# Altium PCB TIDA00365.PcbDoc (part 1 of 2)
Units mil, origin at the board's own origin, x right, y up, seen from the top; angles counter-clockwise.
Board outline 2520 x 2690 mil, 4 copper layers (Top Layer, Mid Layer, GND Layer, Bottom Layer), stack 69.2 mil thick; 171 components, 86 nets, 427 pads, 370 vias.
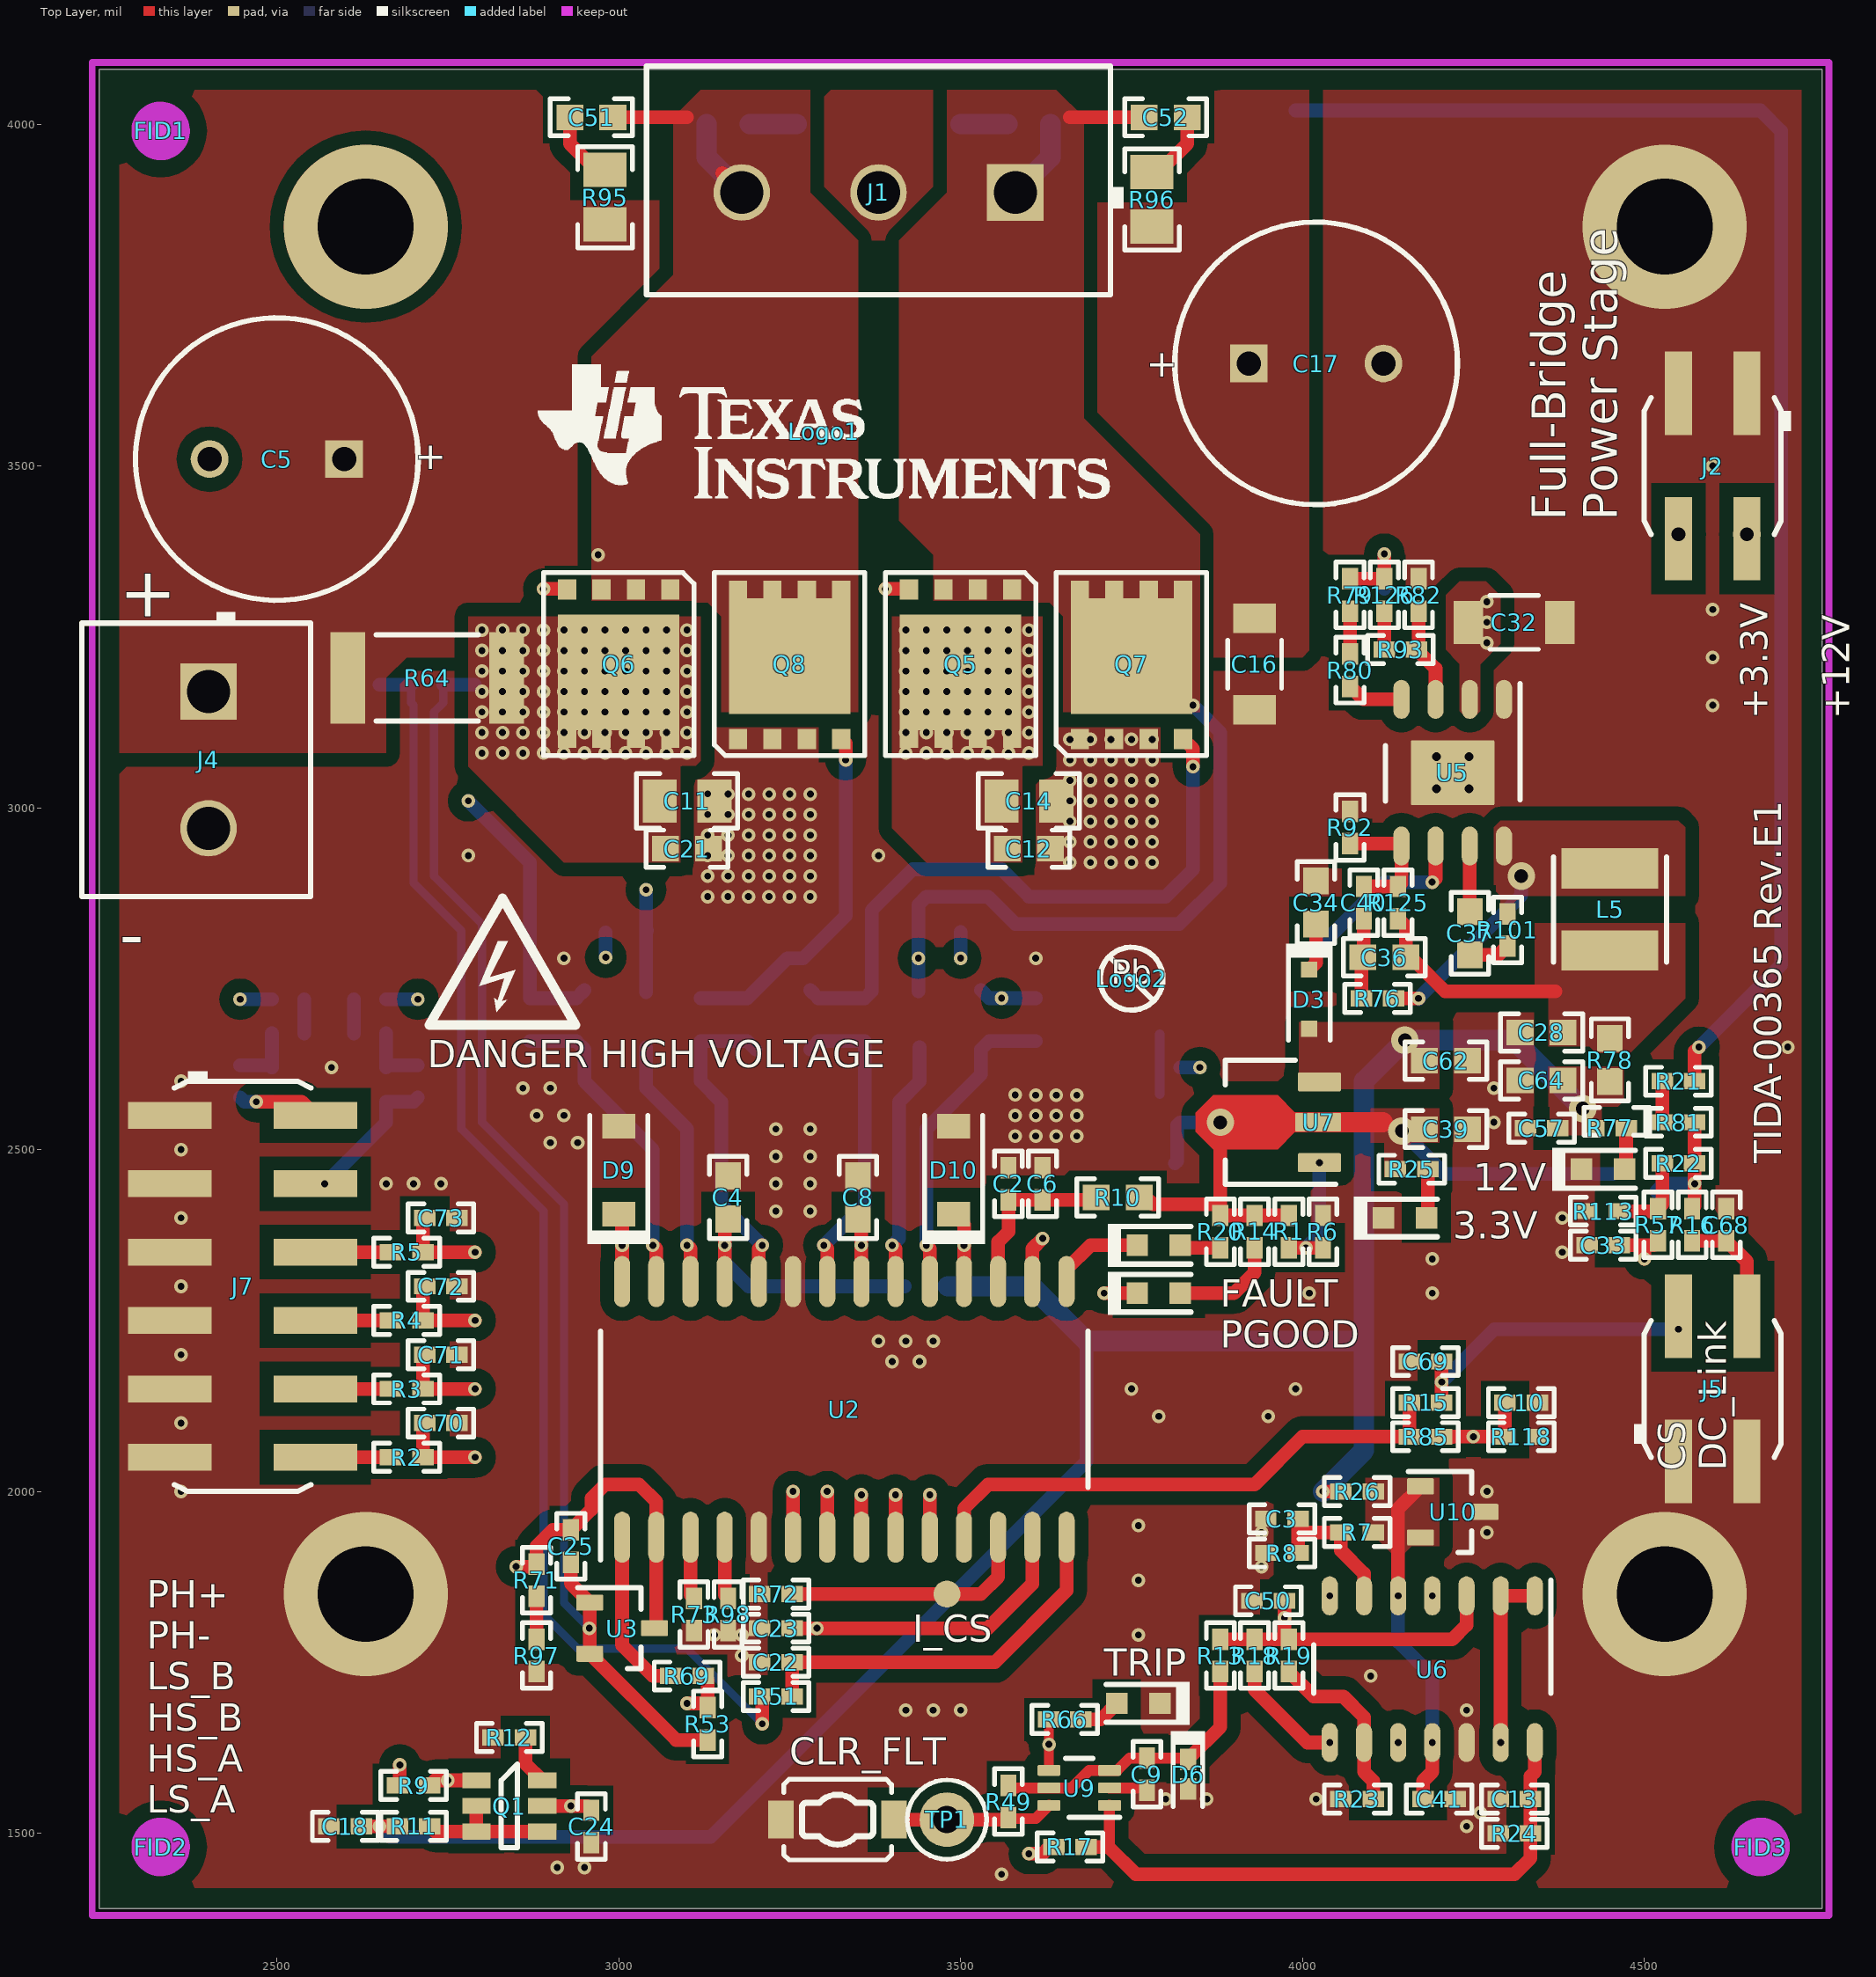
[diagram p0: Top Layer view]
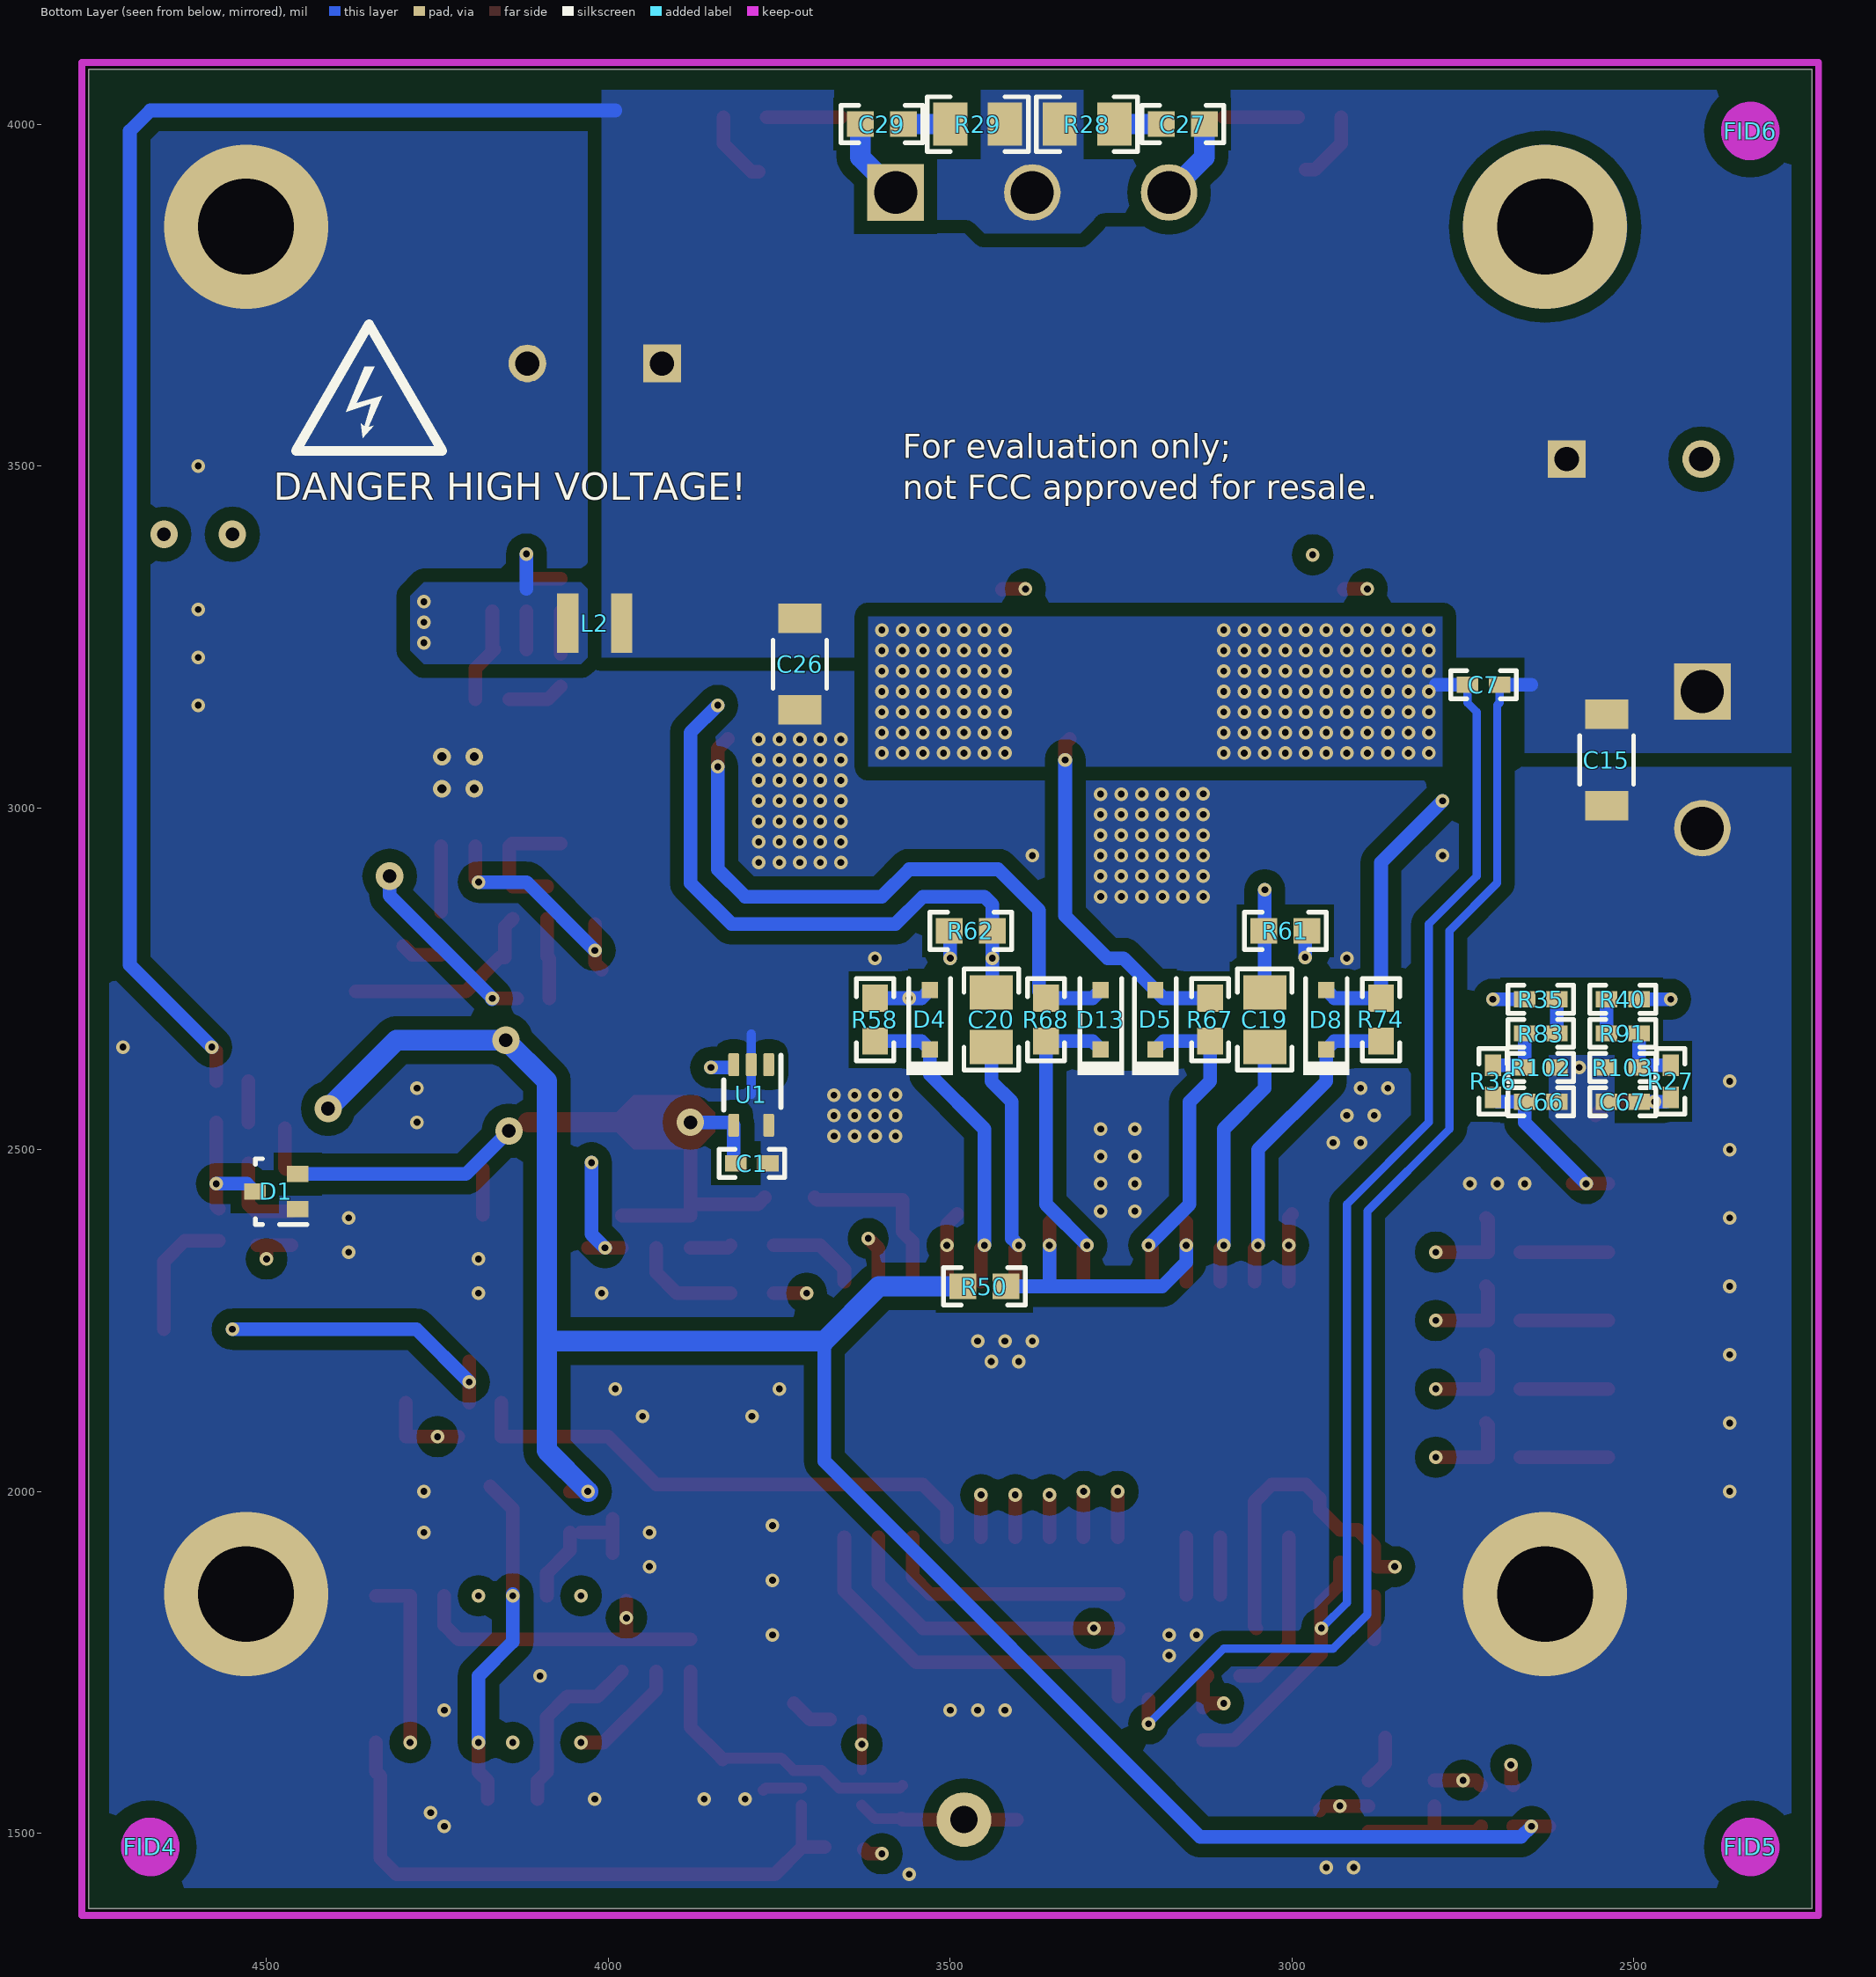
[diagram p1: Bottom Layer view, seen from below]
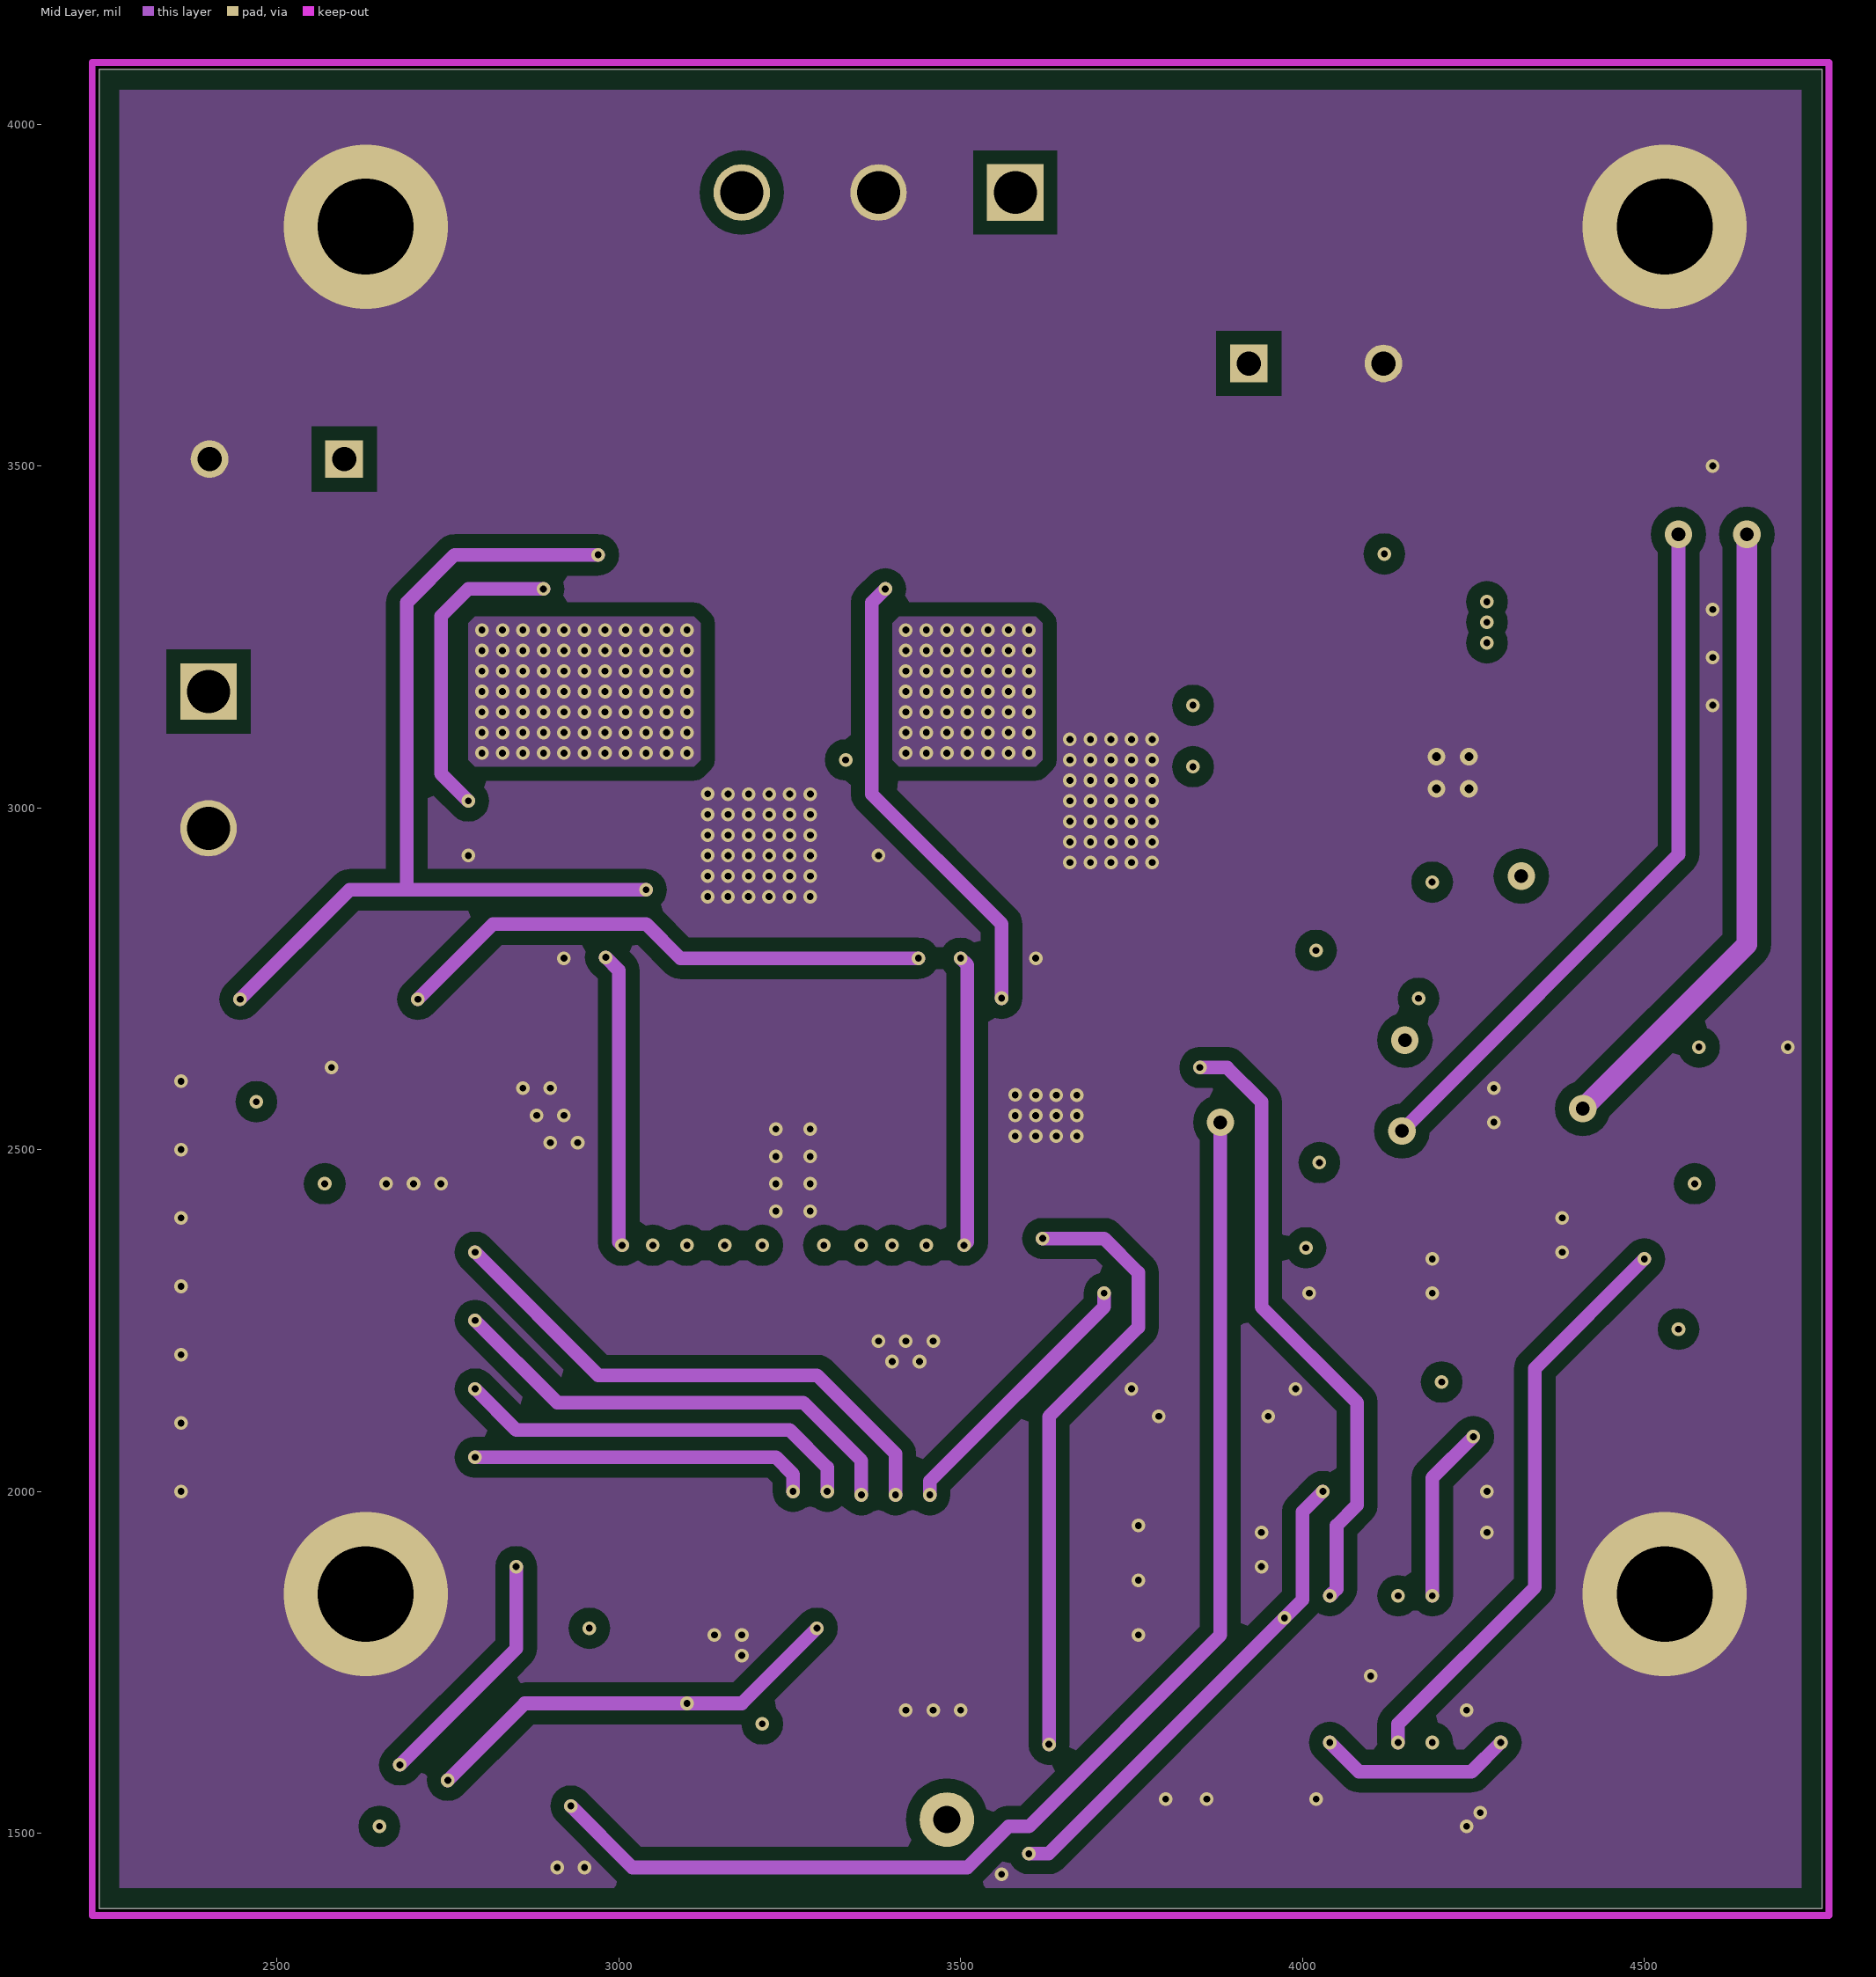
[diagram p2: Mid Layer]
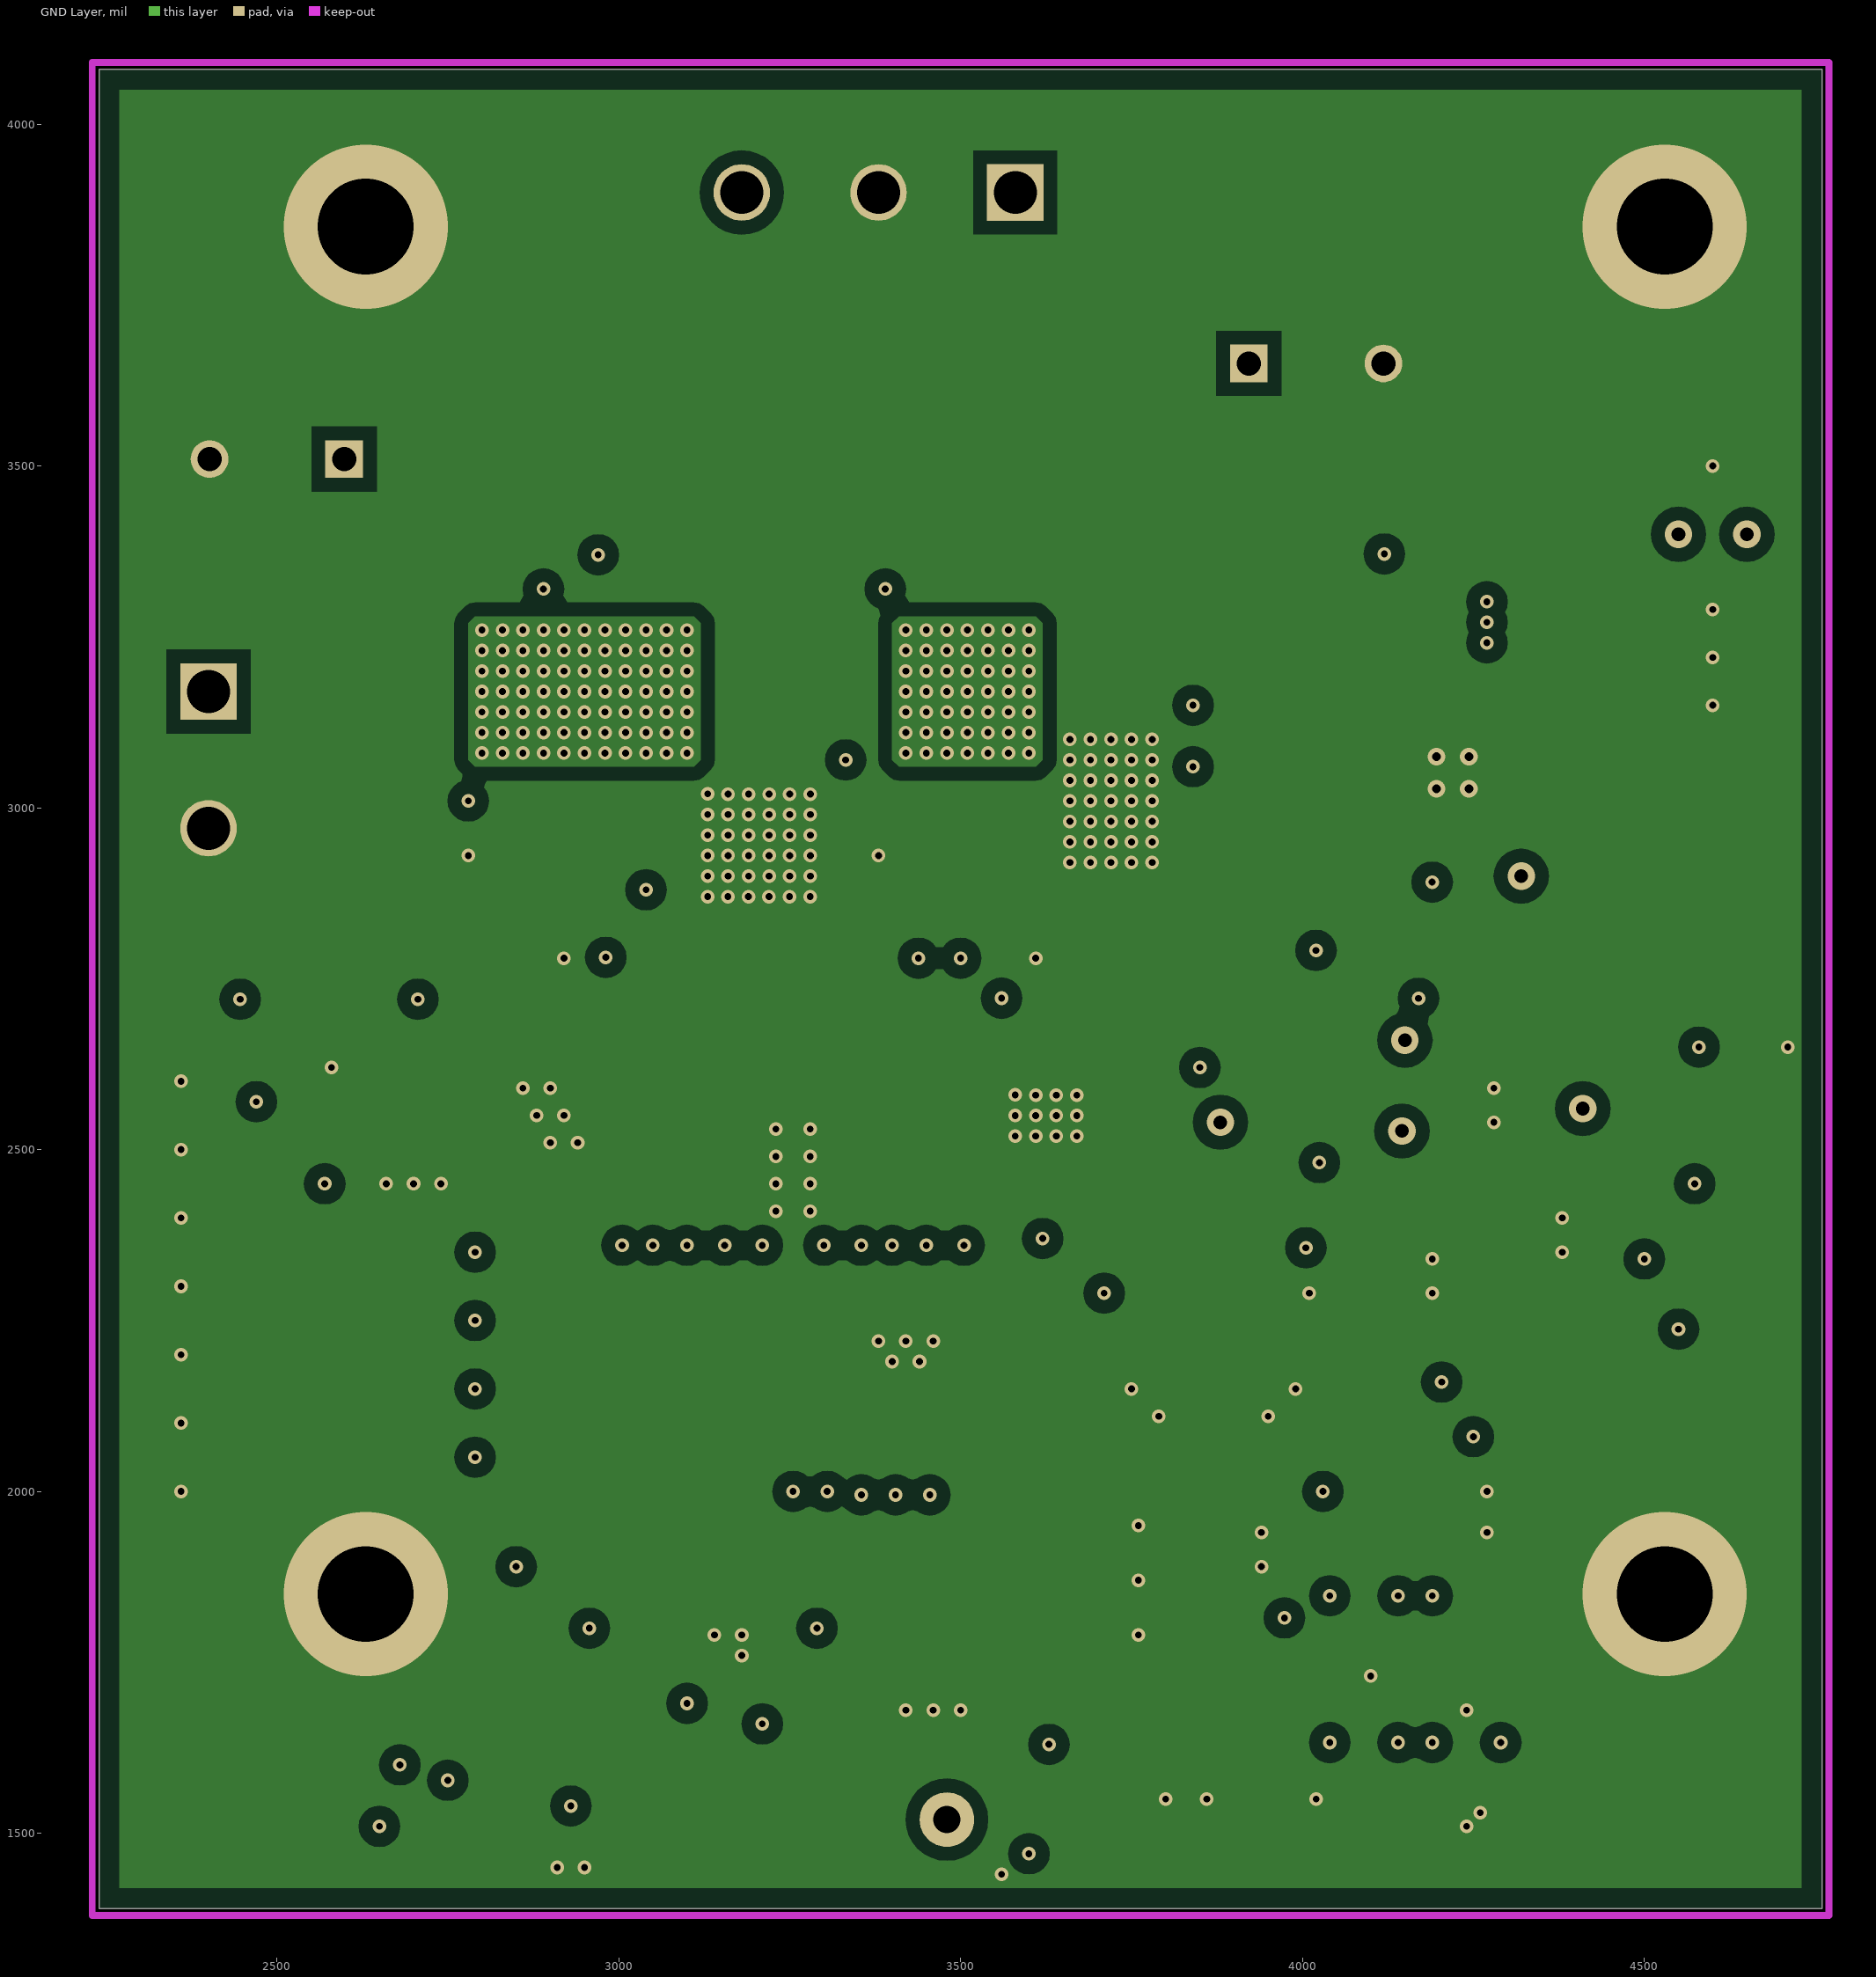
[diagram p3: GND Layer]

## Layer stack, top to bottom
Top Solder: solder mask 0.4, Solder Resist, Dk 3.5
Top Layer: signal copper 2.8
Dielectric: prepreg 12, FR-4, Dk 4.2
Mid Layer: signal copper 2.8
Dielectric: core 34, FR-4, Dk 4.2
GND Layer: signal copper 2.8
Dielectric: prepreg 12, FR-4, Dk 4.2
Bottom Layer: signal copper 2.8
Solder Side: solder mask 0.4, Solder Resist, Dk 3.5

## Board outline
2240,1390 2240,4080 4760,4080 4760,1390

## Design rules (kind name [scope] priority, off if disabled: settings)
AcuteAngle [All] p1: minimum=4.50000000000000E+0001 checktracksonly=FALSE
AssemblyTestPointUsage [All] p1: valid=2
Clearance Clearance_Keepouts [((IsTrack Or IsArc) And Not InPoly) And IsFree and IsKeepOut vs ((IsTrack Or IsArc) And Not InPoly) And IsFree and IsKeepOut] p1: gap=10
Clearance Clearance_BoardEdge_MountingHoles [OnCopper and InComponentClass('Mounting Holes') vs IsKeepOut] p2: gap=10
Clearance Clearance_BoardEdge_Poly [OnCopper and InPoly vs IsKeepOut] p3: gap=25
Clearance Clearance_BoardEdge [OnCopper and Not InComponentClass('Logo') and not InComponentClass('FiducialMark') and not InRegion(1000,500,4000,800) and Not IsKeepout vs IsKeepOut] p4: gap=25
Clearance Clearance_Poly [InPolygon] p5: gap=20
Clearance [All] p6: gap=8
ComponentClearance ComponentClearance_MountingHoles_FiducialMarks [InComponentClass('Mounting Holes') vs InComponentClass('FiducialMark')] p1: gap=20 collisioncheckmode=3 verticalgap=10 showdistances=FALSE
ComponentClearance ComponentClearance_Shunt [InComponentClass('Header') vs InComponentClass('Shunt')] p2: gap=0 collisioncheckmode=3 verticalgap=0 showdistances=FALSE
ComponentClearance ComponentClearance_Logo [InComponentClass('Logo')] p3: gap=10 collisioncheckmode=3 verticalgap=10 showdistances=FALSE
ComponentClearance ComponentClearance_ScrewToNut [(HasFootprint('NY PMS 440 0025 PH')) vs (HasFootprint('Keystone_1902C'))] p4: gap=5 collisioncheckmode=3 verticalgap=10 showdistances=FALSE
ComponentClearance ComponentClearance_MountingHoles [InComponentClass('Mounting Holes')] p5: gap=20 collisioncheckmode=3 verticalgap=100000 showdistances=FALSE
ComponentClearance ComponentClearance_SmallPassives [HasFootprint('0201*') or HasFootprint('0402*') or HasFootprint('0508') or HasFootprint('0603*') or HasFootprint('0612') or HasFootprint('0805*') or HasFootprint('0815*') or HasFootprint('0830*') or HasFootprint('1206*') or HasFootprint('1210*') or HasFootprint('1808*') or HasFootprint('1812*') or HasFootprint('1825*') or HasFootprint('2010*') or HasFootprint('2220*') or HasFootprint('2225*') or HasFootprint('2512*') or HasFootprint('2728*') or HasFootprint('3518*') vs HasFootprint('0201*') or HasFootprint('0402*') or HasFootprint('0508') or HasFootprint('0603*') or HasFootprint('0612') or HasFootprint('0805*') or HasFootprint('0815*') or HasFootprint('0830*') or HasFootprint('1206*') or HasFootprint('1210*') or HasFootprint('1808*') or HasFootprint('1812*') or HasFootprint('1825*') or HasFootprint('2010*') or HasFootprint('2220*') or HasFootprint('2225*') or HasFootprint('2512*') or HasFootprint('2728*') or HasFootprint('3518*')] p6: gap=20 collisioncheckmode=3 verticalgap=10 showdistances=FALSE
ComponentClearance ComponentClearance_THtoSMT [IsThruComponent vs IsSMTComponent] p7: gap=20 collisioncheckmode=3 verticalgap=30 showdistances=FALSE
ComponentClearance ComponentClearance_THtoTH [IsThruComponent vs IsThruComponent] p8: gap=20 collisioncheckmode=3 verticalgap=30 showdistances=FALSE
ComponentClearance [All] p9: gap=25 collisioncheckmode=3 verticalgap=10 showdistances=FALSE
DiffPairsRouting [All] p1: maxlimit=100 minlimit=10 mostfreqgap=10 toplayer_minwidth=15 toplayer_maxwidth=15 toplayer_prefwidth=15 midlayer1_minwidth=15 midlayer1_maxwidth=15 midlayer1_prefwidth=15 midlayer2_minwidth=15 midlayer2_maxwidth=15 midlayer2_prefwidth=15 bottomlayer_minwidth=15 bottomlayer_maxwidth=15 bottomlayer_prefwidth=15 maxuncoupledlength=1000
FabricationTestPointUsage TestPointUsage [All] p1: valid=2 allowmultiple=FALSE
FabricationTestpoint Testpoint [All] p1: side=3 testpointundercomponent=TRUE minsize=40 maxsize=100 preferedsize=60 minholesize=0 maxholesize=40 preferedholesize=32 testpointgrid=1 allowsidetop=TRUE allowsidebottom=TRUE usegrid=TRUE gridtolerance=0.01
FanoutControl Fanout_LCC [IsLCC] p1: bgadir=Out bgaviamode=Centered fanoutstyle=Auto fanoutdirection=Alternating viagrid=1 // Fanout_LCC (Default Rule)
FanoutControl Fanout_BGA [IsBGA] p2: bgadir=Out bgaviamode=Centered fanoutstyle=Auto fanoutdirection=Alternating viagrid=1 // Fanout_BGA (Default Rule)
FanoutControl Fanout_Default [All] p4: bgadir=Out bgaviamode=Centered fanoutstyle=Auto fanoutdirection=Alternating viagrid=1 // Fanout_Default (Default Rule)
FanoutControl Fanout_Small [(CompPinCount < 5)] p5: bgadir=Out bgaviamode=Centered fanoutstyle=Auto fanoutdirection=OutThenIn viagrid=1 // Fanout_Small (Default Rule)
HoleSize [All] p1: absolutevalues=TRUE maxlimit=251 minlimit=8 maxpercent=80.000 minpercent=20.000
MinimumAnnularRing MinimumAnnularRing_ThermalPadVias [IsVia and InAnyComponent] p1: minimumring=6
MinimumAnnularRing [All] p2: minimumring=4
MinimumSolderMaskSliver MinimumSolderMaskSliver_Logo [InComponentClass('Logo') vs InComponentClass('Logo')] p1: minsoldermaskwidth=0.7
MinimumSolderMaskSliver [All] p2: minsoldermaskwidth=0
PlaneConnect [All] p1: planeconnectstyle=Relief reliefexpansion=10 reliefentries=4 reliefconductorwidth=10 reliefairgap=10
PolygonConnect PolygonConnect_59 [All vs IsNamedPolygon('GND_L04_P043')] p1: connectstyle=Direct reliefconductorwidth=10 reliefentries=4 polygonreliefangle="90 Angle" airgapwidth=10
PolygonConnect PolygonConnect_58 [All vs IsNamedPolygon('PROT_VTH_L01_P044')] p2: connectstyle=Direct reliefconductorwidth=10 reliefentries=4 polygonreliefangle="90 Angle" airgapwidth=10
PolygonConnect PolygonConnect_57 [All vs IsNamedPolygon('NONET_L04_P125')] p3: connectstyle=Direct reliefconductorwidth=10 reliefentries=4 polygonreliefangle="90 Angle" airgapwidth=10
PolygonConnect PolygonConnect_56 [All vs IsNamedPolygon('NONET_L04_P127')] p4: connectstyle=Direct reliefconductorwidth=10 reliefentries=4 polygonreliefangle="90 Angle" airgapwidth=10
PolygonConnect PolygonConnect_55 [All vs IsNamedPolygon('HS_CSN_2_L03_P049')] p5: connectstyle=Direct reliefconductorwidth=10 reliefentries=4 polygonreliefangle="90 Angle" airgapwidth=10
PolygonConnect PolygonConnect_54 [All vs IsNamedPolygon('HS_CSN_2_L03_P048')] p6: connectstyle=Direct reliefconductorwidth=10 reliefentries=4 polygonreliefangle="90 Angle" airgapwidth=10
PolygonConnect PolygonConnect_53 [All vs IsNamedPolygon('HS_CSN_2_L02_P050')] p7: connectstyle=Direct reliefconductorwidth=10 reliefentries=4 polygonreliefangle="90 Angle" airgapwidth=10
PolygonConnect PolygonConnect_52 [All vs IsNamedPolygon('HS_CSN_2_L02_P051')] p8: connectstyle=Direct reliefconductorwidth=10 reliefentries=4 polygonreliefangle="90 Angle" airgapwidth=10
PolygonConnect PolygonConnect_51 [All vs IsNamedPolygon('NETC32_1_L01_P052')] p9: connectstyle=Direct reliefconductorwidth=10 reliefentries=4 polygonreliefangle="90 Angle" airgapwidth=10
PolygonConnect PolygonConnect_50 [All vs IsNamedPolygon('HS_CSN_2_L04_P053')] p10: connectstyle=Direct reliefconductorwidth=10 reliefentries=4 polygonreliefangle="90 Angle" airgapwidth=10
PolygonConnect PolygonConnect_49 [All vs IsNamedPolygon('HS_CSN_2_L04_P053')] p11: connectstyle=Direct reliefconductorwidth=10 reliefentries=4 polygonreliefangle="90 Angle" airgapwidth=10
PolygonConnect PolygonConnect_48 [All vs IsNamedPolygon('HS_CSN_2_L01_P054')] p12: connectstyle=Direct reliefconductorwidth=10 reliefentries=4 polygonreliefangle="90 Angle" airgapwidth=10
PolygonConnect PolygonConnect_47 [All vs IsNamedPolygon('PHASEB+_L01_P056')] p13: connectstyle=Direct reliefconductorwidth=10 reliefentries=4 polygonreliefangle="90 Angle" airgapwidth=10
PolygonConnect PolygonConnect_46 [All vs IsNamedPolygon('HS_CSN_2_L01_P057')] p14: connectstyle=Direct reliefconductorwidth=10 reliefentries=4 polygonreliefangle="90 Angle" airgapwidth=10
PolygonConnect PolygonConnect_45 [All vs IsNamedPolygon('HS_CSP_2_L01_P058')] p15: connectstyle=Direct reliefconductorwidth=10 reliefentries=4 polygonreliefangle="90 Angle" airgapwidth=10
PolygonConnect PolygonConnect_44 [All vs IsNamedPolygon('PHASEB+_L01_P056')] p16: connectstyle=Direct reliefconductorwidth=10 reliefentries=4 polygonreliefangle="90 Angle" airgapwidth=10
PolygonConnect PolygonConnect_43 [All vs IsNamedPolygon('PHASEB-_L01_P055')] p17: connectstyle=Direct reliefconductorwidth=10 reliefentries=4 polygonreliefangle="90 Angle" airgapwidth=10
PolygonConnect PolygonConnect_42 [All vs IsNamedPolygon('GND_L02_P079')] p18: connectstyle=Direct reliefconductorwidth=10 reliefentries=4 polygonreliefangle="90 Angle" airgapwidth=10
PolygonConnect PolygonConnect_41 [All vs IsNamedPolygon('GND_L04_P077')] p19: connectstyle=Direct reliefconductorwidth=10 reliefentries=4 polygonreliefangle="90 Angle" airgapwidth=10
PolygonConnect PolygonConnect_40 [All vs IsNamedPolygon('GND_L01_P115')] p20: connectstyle=Direct reliefconductorwidth=10 reliefentries=4 polygonreliefangle="90 Angle" airgapwidth=10
PolygonConnect PolygonConnect_39 [All vs IsNamedPolygon('HS_CSP_2_L04_P063')] p21: connectstyle=Direct reliefconductorwidth=10 reliefentries=4 polygonreliefangle="90 Angle" airgapwidth=10
PolygonConnect PolygonConnect_38 [All vs IsNamedPolygon('HS_CSP_2_L04_P063')] p22: connectstyle=Direct reliefconductorwidth=10 reliefentries=4 polygonreliefangle="90 Angle" airgapwidth=10
PolygonConnect PolygonConnect_37 [All vs IsNamedPolygon('HS_CSP_2_L04_P063')] p23: connectstyle=Direct reliefconductorwidth=10 reliefentries=4 polygonreliefangle="90 Angle" airgapwidth=10
PolygonConnect PolygonConnect_36 [All vs IsNamedPolygon('HS_CSN_2_L04_P072')] p24: connectstyle=Direct reliefconductorwidth=10 reliefentries=4 polygonreliefangle="90 Angle" airgapwidth=10
PolygonConnect PolygonConnect_35 [All vs IsNamedPolygon('HS_CSP_2_L01_P061')] p25: connectstyle=Direct reliefconductorwidth=10 reliefentries=4 polygonreliefangle="90 Angle" airgapwidth=10
PolygonConnect PolygonConnect_34 [All vs IsNamedPolygon('Mid Layer-No Net')] p26: connectstyle=Direct reliefconductorwidth=10 reliefentries=4 polygonreliefangle="90 Angle" airgapwidth=10
PolygonConnect PolygonConnect_33 [All vs IsNamedPolygon('NETC28_1_L01_P073')] p27: connectstyle=Direct reliefconductorwidth=10 reliefentries=4 polygonreliefangle="90 Angle" airgapwidth=10
PolygonConnect PolygonConnect_32 [All vs IsNamedPolygon('Bottom Layer-No Net 4')] p28: connectstyle=Direct reliefconductorwidth=10 reliefentries=4 polygonreliefangle="90 Angle" airgapwidth=10
PolygonConnect PolygonConnect_31 [All vs IsNamedPolygon('GND Layer-No Net')] p29: connectstyle=Direct reliefconductorwidth=10 reliefentries=4 polygonreliefangle="90 Angle" airgapwidth=10
PolygonConnect PolygonConnect_30 [All vs IsNamedPolygon('Top Layer-No Net 16')] p30: connectstyle=Direct reliefconductorwidth=10 reliefentries=4 polygonreliefangle="90 Angle" airgapwidth=10
PolygonConnect PolygonConnect_29 [All vs IsNamedPolygon('Top Layer-No Net 15')] p31: connectstyle=Direct reliefconductorwidth=10 reliefentries=4 polygonreliefangle="90 Angle" airgapwidth=10
PolygonConnect PolygonConnect_28 [All vs IsNamedPolygon('Top Layer-No Net 14')] p32: connectstyle=Direct reliefconductorwidth=10 reliefentries=4 polygonreliefangle="90 Angle" airgapwidth=10
PolygonConnect PolygonConnect_27 [All vs IsNamedPolygon('Top Layer-No Net 13')] p33: connectstyle=Direct reliefconductorwidth=10 reliefentries=4 polygonreliefangle="90 Angle" airgapwidth=10
PolygonConnect PolygonConnect_26 [All vs IsNamedPolygon('NETL5_1_L01_P067')] p34: connectstyle=Direct reliefconductorwidth=10 reliefentries=4 polygonreliefangle="90 Angle" airgapwidth=10
PolygonConnect PolygonConnect_25 [All vs IsNamedPolygon('+12V_L01_P064')] p35: connectstyle=Direct reliefconductorwidth=10 reliefentries=4 polygonreliefangle="90 Angle" airgapwidth=10
PolygonConnect PolygonConnect_24 [All vs IsNamedPolygon('+12V_L01_P074')] p36: connectstyle=Direct reliefconductorwidth=10 reliefentries=4 polygonreliefangle="90 Angle" airgapwidth=10
PolygonConnect PolygonConnect_23 [All vs IsNamedPolygon('Bottom Layer-No Net 3')] p37: connectstyle=Direct reliefconductorwidth=10 reliefentries=4 polygonreliefangle="90 Angle" airgapwidth=10
PolygonConnect PolygonConnect_22 [All vs IsNamedPolygon('Bottom Layer-No Net 2')] p38: connectstyle=Direct reliefconductorwidth=10 reliefentries=4 polygonreliefangle="90 Angle" airgapwidth=10
PolygonConnect PolygonConnect_21 [All vs IsNamedPolygon('Bottom Layer-No Net 1')] p39: connectstyle=Direct reliefconductorwidth=10 reliefentries=4 polygonreliefangle="90 Angle" airgapwidth=10
PolygonConnect PolygonConnect_20 [All vs IsNamedPolygon('Bottom Layer-No Net')] p40: connectstyle=Direct reliefconductorwidth=10 reliefentries=4 polygonreliefangle="90 Angle" airgapwidth=10
PolygonConnect PolygonConnect_19 [All vs IsNamedPolygon('Bottom Layer-No Net 1')] p41: connectstyle=Direct reliefconductorwidth=10 reliefentries=4 polygonreliefangle="90 Angle" airgapwidth=10
PolygonConnect PolygonConnect_18 [All vs IsNamedPolygon('GND_L03_P078')] p42: connectstyle=Direct reliefconductorwidth=10 reliefentries=4 polygonreliefangle="90 Angle" airgapwidth=10
PolygonConnect PolygonConnect_17 [All vs IsNamedPolygon('GND_L03_P078')] p43: connectstyle=Direct reliefconductorwidth=10 reliefentries=4 polygonreliefangle="90 Angle" airgapwidth=10
PolygonConnect PolygonConnect_16 [All vs IsNamedPolygon('GND_L03_P078')] p44: connectstyle=Direct reliefconductorwidth=10 reliefentries=4 polygonreliefangle="90 Angle" airgapwidth=10
PolygonConnect PolygonConnect_15 [All vs IsNamedPolygon('GND_L03_P078')] p45: connectstyle=Direct reliefconductorwidth=10 reliefentries=4 polygonreliefangle="90 Angle" airgapwidth=10
PolygonConnect PolygonConnect_14 [All vs IsNamedPolygon('GND_L03_P078')] p46: connectstyle=Direct reliefconductorwidth=10 reliefentries=4 polygonreliefangle="90 Angle" airgapwidth=10
PolygonConnect PolygonConnect_13 [All vs IsNamedPolygon('NETC32_1_L04_P065')] p47: connectstyle=Direct reliefconductorwidth=10 reliefentries=4 polygonreliefangle="90 Angle" airgapwidth=10
PolygonConnect PolygonConnect_12 [All vs IsNamedPolygon('NETL5_1_L01_P067')] p48: connectstyle=Direct reliefconductorwidth=10 reliefentries=4 polygonreliefangle="90 Angle" airgapwidth=10
PolygonConnect PolygonConnect_11 [All vs IsNamedPolygon('+3V3_L01_P045')] p49: connectstyle=Direct reliefconductorwidth=10 reliefentries=4 polygonreliefangle="90 Angle" airgapwidth=10
PolygonConnect PolygonConnect_10 [All vs IsNamedPolygon('+3V3_L01_P045')] p50: connectstyle=Direct reliefconductorwidth=10 reliefentries=4 polygonreliefangle="90 Angle" airgapwidth=10
PolygonConnect PolygonConnect_9 [All vs IsNamedPolygon('NETC32_1_L04_P065')] p51: connectstyle=Direct reliefconductorwidth=10 reliefentries=4 polygonreliefangle="90 Angle" airgapwidth=10
PolygonConnect PolygonConnect_8 [All vs IsNamedPolygon('NETL5_1_L01_P067')] p52: connectstyle=Direct reliefconductorwidth=10 reliefentries=4 polygonreliefangle="90 Angle" airgapwidth=10
PolygonConnect PolygonConnect_7 [All vs IsNamedPolygon('NETC28_1_L01_P073')] p53: connectstyle=Direct reliefconductorwidth=10 reliefentries=4 polygonreliefangle="90 Angle" airgapwidth=10
PolygonConnect PolygonConnect_6 [All vs IsNamedPolygon('+3V3_L01_P045')] p54: connectstyle=Direct reliefconductorwidth=10 reliefentries=4 polygonreliefangle="90 Angle" airgapwidth=10
PolygonConnect PolygonConnect_5 [All vs IsNamedPolygon('+3V3_L01_P045')] p55: connectstyle=Direct reliefconductorwidth=10 reliefentries=4 polygonreliefangle="90 Angle" airgapwidth=10
PolygonConnect PolygonConnect_4 [All vs IsNamedPolygon('Top Layer-No Net 3')] p56: connectstyle=Direct reliefconductorwidth=10 reliefentries=4 polygonreliefangle="90 Angle" airgapwidth=10
PolygonConnect PolygonConnect_3 [All vs IsNamedPolygon('Top Layer-No Net 1')] p57: connectstyle=Direct reliefconductorwidth=10 reliefentries=4 polygonreliefangle="90 Angle" airgapwidth=10
PolygonConnect PolygonConnect_2 [All vs IsNamedPolygon('+12V_L01_P064')] p58: connectstyle=Direct reliefconductorwidth=10 reliefentries=4 polygonreliefangle="90 Angle" airgapwidth=10
PolygonConnect PolygonConnect_1 [All vs IsNamedPolygon('GND_L03_P078')] p59: connectstyle=Direct reliefconductorwidth=10 reliefentries=4 polygonreliefangle="90 Angle" airgapwidth=10
PolygonConnect [All] p60: connectstyle=Direct reliefconductorwidth=10 reliefentries=4 polygonreliefangle="90 Angle" airgapwidth=10
RoutingVias ThermalPadVias [IsVia and InAnyComponent] p1: holewidth=10 width=20 viastyle="Through Hole" minholewidth=5 minwidth=15 maxholewidth=25 maxwidth=45
RoutingVias [All] p2: holewidth=10 width=20 viastyle="Through Hole" minholewidth=5 minwidth=10 maxholewidth=200 maxwidth=300
SilkToBoardRegionClearance [Not ((IsComment or IsDesignator) And (Hide <> 'False')) and not InRegion(1000,500,4000,800)] p1:
SilkToSilkClearance SilkToSilkClearance_Pb-FreeLogo [(HasFootprint('Pb-Free_Overlay_Medium') OR HasFootprint('Pb-Free_Overlay_Small')) vs (HasFootprint('Pb-Free_Overlay_Medium') OR HasFootprint('Pb-Free_Overlay_Small'))] p1: silktosilkclearance=0
SilkToSilkClearance [All] p2: silktosilkclearance=0
SilkToSolderMaskClearance SilkToComonentPadClearance [IsPad and InAnycomponent] p1: minsilkscreentomaskgap=0 clearancetoexposedcopper=TRUE
SilkToSolderMaskClearance "Silk to Solder Mask Opening" [All] p2: minsilkscreentomaskgap=0 clearancetoexposedcopper=FALSE
SolderMaskExpansion [All] p1: expansion=1.97
Width [All] p1: maxlimit=200 minlimit=5 preferedwidth=20 checkconnectedcopper=TRUE
15 further rules are at their usual default settings.

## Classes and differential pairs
component class Logo: Logo1
component class TIDA00365_Screws: "DANGER HIGH VOLTAGE" "DANGER HIGH VOLTAGE1" "DANGER HIGH VOLTAGE!" FID1 FID2 FID3 FID4 FID5 FID6 Logo1 Logo2 Logo3
component class Header: J2 J5 J7
component class Protections: C1 C3 C9 C10 C13 C33 C41 C50 CLR_FLT D1 D6 R7 R8 R13 R17 R18 R19 R21 R22 R23 R24 R26 R49 R57 R66 R81 R85 R113 R118 R? TP1 TRIP U1 U6 U9 U10
component class "Full Bridge": C2 C4 C6 C7 C8 C11 C12 C14 C18 C19 C20 C21 C22 C23 C24 C25 C27 C29 C51 C52 D4 D5 D8 D9 D10 D13 FAULT I_CS PGOOD Q1 Q5 Q6 Q7 Q8 R9 R10 R11 R12 R14 R20 R28 R29 R50 R51 R53 R58 R61 R62 R64 R67 R68 R69 R71 R72 R73 R74 R95 R96 R97 R98 U2 U3
component class "Power Supply": 3.3V 4V 12V C5 C15 C16 C17 C26 C28 C32 C34 C36 C37 C39 C40 C57 C62 C64 D3 J2 J4 L2 L5 R1 R6 R25 R76 R77 R78 R79 R80 R82 R92 R93 R101 R125 R126 U5 U7
component class Interfaces: C66 C67 C68 C69 C70 C71 C72 C73 J1 J5 J7 R2 R3 R4 R5 R15 R16 R27 R35 R36 R40 R83 R91 R102 R103
component class FiducialMark: FID1 FID2 FID3 FID4 FID5 FID6

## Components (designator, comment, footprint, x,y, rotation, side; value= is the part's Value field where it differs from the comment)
3.3V "150060GS75000" WL-SMCW_GREEN 4150,2400 r0 top
12V "150060GS75000" WL-SMCW_GREEN 4439.8,2471.3 r0 top
C1 "C1005X7R1E104M050BB" 0402#1 3790,2480 r180 bottom
C2 "885012205031" 0402#1 3570,2450 r90 top
C3 "885012105016" 0402#1 3970,1960 r180 top
C4 "885012106017" 0603 3160,2430 r270 top
C5 "860040875005" WCAP-ATUL_1000x2500 2500,3510 r180 top
C6 "C1005X7R1E104M050BB" 0402#1 3620,2450 r90 top
C7 "GRM155R72A472KA01D" 0402#1 2720,3180 r0 bottom
C8 "885012106017" 0603 3350,2430 r270 top
C9 "885012205031" 0402#1 3772.65,1586.38 r270 top
C10 "CC0402KRX7R9BB101" 0402#1 4320,2130 r0 top
C11 "C2012X7S2A105K125AB" 0805_HV 3100,3010 r0 top
C12 "06031C103KAT2A" 0603 3600,2940 r0 top
C13 "CC0402KRX7R9BB101" 0402#1 4310,1550 r180 top
C14 "C2012X7S2A105K125AB" 0805_HV 3600,3010 r0 top
C15 "C3216X7S2A335M160AB" 1206_190 2540,3070 r270 bottom
C16 "C3216X7S2A335M160AB" 1206_190 3930,3210 r270 top
C17 "860040875005" WCAP-ATUL_1000x2500 4020,3650 r0 top
C18 "885012205031" 0402#1 2600,1510 r180 top
C19 "C2012X7R2A104K125AA" 0805_HV 3040,2690 r90 bottom
C20 "C2012X7R2A104K125AA" 0805_HV 3440,2690 r90 bottom
C21 "06031C103KAT2A" 0603 3100,2940 r0 top
C22 "885012205055" 0402#1 3230,1750 r0 top
C23 "885012205055" 0402#1 3230,1800 r180 top
C24 "885012205031" 0402#1 2960,1510 r270 top
C25 "885012205055" 0402#1 2930,1920 r90 top
C26 "C3216X7S2A335M160AB" 1206_190 3720,3210 r270 bottom
C27 "06031C222JAT2A" 0603 3160,4000 r180 bottom
C28 "GRM188R61E475KE11D" 0603 4349.8,2671.3 r180 top
C29 "06031C222JAT2A" 0603 3600,4000 r0 bottom
C32 "C3216X7S2A335M160AB" 1206_190 4309.8,3271.3 r0 top
C33 "CC0402KRX7R9BB101" 0402#1 4440,2360 r180 top
C34 "C1608X5R1C105K" 0603 4019.8,2861.3 r90 top
C36 "GRM188R72A332KA01D" 0603 4119.8,2781.3 r180 top
C37 "GRM188R72A104KA35D" 0603 4244.8,2816.3 r270 top
C39 "C1608X5R1C105K" 0603 4210,2530 r0 top
C40 "C1005X7R1E104M050BB" 0402#1 4089.8,2861.3 r90 top
C41 "885012205044" 0402#1 4200,1550 r0 top
C50 "C1005X7R1E104M050BB" 0402#1 3950,1840 r180 top
C51 "06031C222JAT2A" 0603 2960,4010 r0 top
C52 "06031C222JAT2A" 0603 3800,4010 r180 top
C57 "C1005X7R1E104M050BB" 0402#1 4349.8,2531.3 r180 top
C62 "C1608X5R1C105K" 0603 4210,2630 r0 top
C64 "GRM188R61E475KE11D" 0603 4349.8,2601.3 r180 top
C66 "CC0402KRX7R9BB101" 0402#1 2636.38,2570 r0 bottom
C67 "CC0402KRX7R9BB101" 0402#1 2516.38,2570 r180 bottom
C68 "CC0402KRX7R9BB101" 0402#1 4620,2390 r270 top
C69 "CC0402KRX7R9BB101" 0402#1 4180,2190 r0 top
C70 "CC0402KRX7R9BB101" 0402#1 2740,2100 r0 top
C71 "CC0402KRX7R9BB101" 0402#1 2740,2200 r0 top
C72 "CC0402KRX7R9BB101" 0402#1 2740,2300 r0 top
C73 "CC0402KRX7R9BB101" 0402#1 2740,2400 r0 top
CLR_FLT "TL1015AF160QG" SW_TL1015AF160QG 3320,1520 r0 top
D1 "BAV99W-7-F" SOT-323 4485.75,2438.6 r0 bottom
D3 "BAS316,115" sod-323 4010,2720 r270 top
D4 "BAS316,115" sod-323 3530,2690 r90 bottom
D5 "BAS316,115" sod-323 3200,2690 r90 bottom
D6 "BZT52C3V9T-7" SOD-523 3832.65,1586.38 r270 top
D8 "BAS316,115" sod-323 2950,2690 r90 bottom
D9 "MMSZ5270BT1G" SOD-123 3000,2470 r90 top
D10 "MMSZ5270BT1G" SOD-123 3490,2470 r90 top
D13 "BAS316,115" sod-323 3280,2690 r90 bottom
"DANGER HIGH VOLTAGE" "DANGER HIGH VOLTAGE" IEC_HighVoltage_Small 2830,2770 r0 top
"DANGER HIGH VOLTAGE!" "DANGER HIGH VOLTAGE" IEC_HighVoltage_Small 4350,3610 r180 bottom
FAULT "150060RS75000" WL-SMCW_RED 3790,2360 r0 top
FID1 "Fiducial" Fiducial6.4-20 2330,3990 r270 top
FID2 "Fiducial" Fiducial6.4-20 2330,1480 r270 top
FID3 "Fiducial" Fiducial6.4-20 4670,1480 r0 top
FID4 "Fiducial" Fiducial6.4-20 4670,1480 r180 bottom
FID5 "Fiducial" Fiducial6.4-20 2330,1480 r180 bottom
FID6 "Fiducial" Fiducial6.4-20 2330,3990 r180 bottom
I_CS "TESTPOINT" TP_SM_1MM 3480,1850 r90 top
J1 "691311500103" Wurth_691311500103 3380,3900 r180 top
J2 "61030421121" Wurth_61030421121 4600,3500 r270 top
J4 "691311500002" Wurth_691311500002 2400,3070 r270 top
J5 "61030421121" Wurth_61030421121 4600,2150 r90 top
J7 "61031221121" Wurth_61031221121 2450,2300 r0 top
L2 "74479887310" WE-PMI_1008 4020,3270 r0 bottom
L5 "74404041101" WE-LQS_4012 4449.8,2851.3 r270 top
Logo1 "Texas Instruments" TI_Stacked_Overlay_Small 3300,3550 r0 top
Logo2 "Pb-Free Symbol" Pb-Free_Overlay_Small 3750,2750 r0 top
Logo3 "FCC disclaimer" FCC_disclaimer 1970,2060 r270 bottom
PGOOD "150060RS75000" WL-SMCW_RED 3790,2290 r0 top
Q1 "DMMT5551-7-F" SOT-26 2840,1540 r0 top
Q5 "CSD19534Q5A" TRANS_NexFET_Q5A 3500,3210 r270 top
Q6 "CSD19534Q5A" TRANS_NexFET_Q5A 3000,3210 r270 top
Q7 "CSD19534Q5A" TRANS_NexFET_Q5A 3750,3210 r90 top
Q8 "CSD19534Q5A" TRANS_NexFET_Q5A 3250,3210 r90 top
R1 "CRCW0402475RFKED" 0402#1 3980,2380 r90 top
R2 "CRCW040222R0JNED" 0402#1 2690,2050 r0 top
R3 "CRCW040222R0JNED" 0402#1 2690,2150 r0 top
R4 "CRCW040222R0JNED" 0402#1 2690,2250 r0 top
R5 "CRCW040222R0JNED" 0402#1 2690,2350 r0 top
R6 "CRCW0402806RFKED" 0402#1 4030,2380 r270 top
R7 "CRCW0402487KFKED" 0402#1 4080,1940 r0 top
R8 "CRCW0402100KFKED" 0402#1 3970,1910 r0 top
R9 "CRCW04020000Z0ED" 0402#1 2700,1570 r0 top
R10 "CRCW060310R0JNEA" 0603 3730,2430 r0 top
R11 "CRCW040224K0JNED" 0402#1 2700,1510 r180 top
R12 "CRCW040233K2FKED" 0402#1 2840,1640 r0 top
R13 "CRCW04021K20JNED" 0402#1 3880,1760 r90 top
R14 "CRCW04021K20JNED" 0402#1 3930,2380 r90 top
R15 "CRCW040222R0JNED" 0402#1 4180,2130 r180 top
R16 "CRCW040222R0JNED" 0402#1 4570,2390 r90 top
R17 "CRCW0402100KJNED" 0402#1 3660,1480 r180 top
R18 "CRCW040251K0JNED" 0402#1 3930,1760 r270 top
R19 "CRCW040251K0JNED" 0402#1 3980,1760 r270 top
R20 "CRCW04021K20JNED" 0402#1 3880,2380 r90 top
R21 "CRCW040249K9FKED" 0402#1 4550,2600 r0 top
R22 "CRCW04021K00FKED" 0402#1 4550,2480 r0 top
R23 "CRCW040251K0JNED" 0402#1 4080,1550 r180 top
R24 "CRCW040251K0JNED" 0402#1 4310,1500 r0 top
R25 "CRCW0402820RJNED" 0402#1 4159.8,2471.3 r180 top
R26 "CRCW04026K80JNED" 0402#1 4080,2000 r180 top
R27 "CRCW040222R0JNED" 0402#1 2446.38,2600 r90 bottom
R28 "CRCW08052R70JNEA" 0805_HV 3300,4000 r0 bottom
R29 "CRCW08052R70JNEA" 0805_HV 3460,4000 r180 bottom
R35 "CRCW040249K9FKED" 0402#1 2636.38,2720 r0 bottom
R36 "CRCW040222R0JNED" 0402#1 2706.38,2600 r90 bottom
R40 "CRCW040249K9FKED" 0402#1 2516.38,2720 r180 bottom
R49 "CRCW040251K0JNED" 0402#1 3570,1546.38 r90 top
R50 "CRCW060310R0JNEA" 0603 3450,2300 r0 bottom
R51 "CRCW04021K50FKED" 0402#1 3230,1700 r180 top
R53 "CRCW04021K50FKED" 0402#1 3130,1660 r270 top
R57 "CRCW0402100RJNED" 0402#1 4520,2390 r90 top
R58 "CRCW060347R0JNEA" 0603 3610,2690 r90 bottom
R61 "CRCW06033R00JNEA" 0603 3010,2820 r0 bottom
R62 "CRCW06033R00JNEA" 0603 3470,2820 r180 bottom
R64 "CRA2512-FZ-R010ELF" 2512 2720,3190 r180 top
R66 "CRCW04021K80JNED" 0402#1 3652.28,1666.38 r0 top
R67 "CRCW060347R0JNEA" 0603 3120,2690 r90 bottom
R68 "CRCW060347R0JNEA" 0603 3360,2690 r270 bottom
R69 "CRCW040223K2FKED" 0402#1 3100,1730 r0 top
R71 "CRCW0402180KJNED" 0402#1 2880,1870 r270 top
R72 "CRCW040216K5FKED" 0402#1 3230,1850 r0 top
R73 "CRCW040210K0JNED" 0402#1 3110,1820 r90 top
R74 "CRCW060347R0JNEA" 0603 2870,2690 r90 bottom
R76 "CRCW040251K0JNED" 0402#1 4109.8,2721.3 r180 top
R77 "CRCW04029K10JNED" 0402#2 4459.8,2541.3 r180 top
R78 "CRCW060310R0JNEA" 0603 4449.8,2631.3 r270 top
R79 "CRCW0402200KJNED" 0402#1 4069.8,3311.3 r270 top
R80 "CRCW0402200KJNED" 0402#1 4069.8,3201.3 r270 top
R81 "CRCW040249K9FKED" 0402#1 4550,2540 r180 top
R82 "CRCW04027K50JNED" 0402#1 4169.8,3311.3 r270 top
R83 "CRCW040249K9FKED" 0402#1 2636.38,2670 r180 bottom
R85 "CRCW04023K24FKED" 0402#1 4180,2080 r0 top
R91 "CRCW040249K9FKED" 0402#1 2516.38,2670 r0 bottom
R92 "CRCW04022K26FKED" 0402#1 4069.8,2971.3 r270 top
R93 "CRCW040251K0JNED" 0402#1 4143.43,3231.3 r0 top
R95 "CRCW08052R70JNEA" 0805_HV 2980,3893.2 r270 top
R96 "CRCW08052R70JNEA" 0805_HV 3780,3890 r270 top
R97 "CRCW0402180KJNED" 0402#1 2880,1760 r90 top
R98 "CRCW040210K0JNED" 0402#1 3160,1820 r90 top
R101 "CRCW04023R00JNED" 0402#1 4299.8,2821.3 r90 top
R102 "CRCW04023K32FKED" 0402#1 2636.38,2620 r0 bottom
R103 "CRCW04023K32FKED" 0402#1 2516.38,2620 r180 bottom
R113 "CRCW04023K09FKED" 0402#1 4440,2410 r0 top
R118 "CRCW040210K0FKED" 0402#1 4320,2080 r180 top
R125 "CRCW040220K0FKED" 0402#1 4139.8,2861.3 r270 top
R126 "CRCW040251K0JNED" 0402#1 4119.8,3311.3 r270 top
TP1 "5002" Keystone5002 3480,1520 r90 top
TRIP "150060RS75000" WL-SMCW_RED 3760,1690 r180 top
U1 "LMT89DCKR" DCK0005A_N 3791.11,2579.95 r270 bottom
U2 "SM72295MAX/NOPB" DW0028A_N 3330,2120 r90 top
U3 "ATL431BQDBZR" DBZ0003A_N 3005,1800 r0 top
U5 "LM5018MRX/NOPB" DDA0008B_N 4219.8,3051.3 r270 top
U6 "LM2901VQD" D0014A_N 4190,1740 r270 top
U7 "LM317LIPK" PK0003A_N 3950,2540 r180 top
U9 "SN74LVC1G175DCKR" DCK0006A_N 3673.62,1566.38 r180 top
U10 "TL431QDBZT" DBZ0003A_N 4220,1970 r0 top

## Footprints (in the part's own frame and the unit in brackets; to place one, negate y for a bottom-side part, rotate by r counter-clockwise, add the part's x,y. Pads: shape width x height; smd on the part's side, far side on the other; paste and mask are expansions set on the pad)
0402#1 [mm] "0402 from SM-752 data"
  rect 0.8x0.6 smd: 1(-0.6,0) 2(0.6,0)
  silkscreen extent -1.22,-0.52 1.22,0.52, body extent -0.55,-0.3 0.55,0.3, height 0.6
0402#2 [mm] "0402 from SM-752 data"
  rect 0.8x0.6 smd: 1(-0.346,0.254) 2(0.854,0.254)
  silkscreen extent -1.22,-0.52 1.22,0.52, body extent -0.55,-0.3 0.55,0.3, height 0.6
0603 [mm] "0603 from SM-752 data"
  rect 1x0.95 smd: 1(-0.8,0) 2(0.8,0)
  silkscreen extent -1.52,-0.69 1.52,0.69, body extent -0.87,-0.47 0.87,0.47, height 1
0805_HV [mil] "0805 with 30mil clearance between pads"
  rect 50x63 smd: 1(-40,0) 2(40,0)
  silkscreen extent -74,-40 74,40, body extent -43,-29 43,29, height 57
1206_190 [mm] "1206_190"
  rect 1.1x1.6 smd: 1(-1.7,0) 2(1.7,0)
  silkscreen extent -0.9,-1 0.9,1, body extent -1.75,-0.95 1.75,0.95, height 1.9
2512 [mm] "Chip Resistor, Body 6.3x3.2mm, IPC Medium Density"
  rect 1.3x3.4 smd: 1(-2.95,0) 2(2.95,0)
  silkscreen extent -1.9,-1.6 1.9,1.6, body extent -3.22,-1.67 3.22,1.67, height 0.71
D0014A_N [mm] "SOIC, 14-Leads, Body 8.7x3.9mm, Pitch 1.27mm, IPC Medium Density"
  oval 1.45x0.6 smd: 1(-2.725,3.81) 2(-2.725,2.54) 3(-2.725,1.27) 4(-2.725,0) 5(-2.725,-1.27) 6(-2.725,-2.54) 7(-2.725,-3.81) 8(2.725,-3.81) 9(2.725,-2.54) 10(2.725,-1.27) 11(2.725,0) 12(2.725,1.27) 13(2.725,2.54) 14(2.725,3.81)
  silkscreen extent -3.3,-4.4 0.9,4.4, body extent -3.02,-4.32 3.02,4.32, height 1.6
DBZ0003A_N [mm] "SOT23, 3-Leads, Body 2.9x1.3mm, Pitch 0.95mm, Lead Span 2.4mm, IPC Medium Density"
  rrect17% 1x0.6 smd: 1(-1.2,0.95) 2(-1.2,-0.95) 3(1.2,0)
  silkscreen extent -1.65,-1.5 0.7,1.5, body extent -1.26,-1.46 1.26,1.46, height 0.98
DCK0005A_N [mm] "SOT353, 5-Leads, Body 2x1.3mm, Pitch 0.65mm, Lead Span 2.1mm, IPC Medium Density"
  rrect25% 0.85x0.4 smd: 1(-1.125,0.65) 2(-1.125,0) 3(-1.125,-0.65) 4(1.125,-0.65) 5(1.125,0.65)
  silkscreen extent -1.48,-1.02 0.55,1.1, body extent -1.14,-1 1.14,1, height 0.95
DCK0006A_N [mm] "SOT23, 6-Leads, Body 2x1.3mm, Pitch 0.65mm, Lead Span 2.1mm, IPC Medium Density"
  rrect25% 0.85x0.4 smd: 1(-1.125,0.65) 2(-1.125,0) 3(-1.125,-0.65) 4(1.125,-0.65) 5(1.125,0) 6(1.125,0.65)
  silkscreen extent -1.5,-1.09 0.51,1.09, body extent -1.14,-1 1.14,1, height 0.95
DDA0008B_N [mm] "SOIC, 8-Leads, Body 4.9x3.9mm, Pitch 1.27mm, Exposed Pad, IPC Medium Density"
  rrect100% 1.45x0.6 smd: 1(-2.725,1.905) 2(-2.725,0.635) 3(-2.725,-0.635) 4(-2.725,-1.905) 5(2.725,-1.905) 6(2.725,-0.635) 7(2.725,0.635) 8(2.725,1.905)
  rrect4% 2.41x3.1 smd: 9(0,0)
  silkscreen extent -3.3,-2.5 1.05,2.5, body extent -2.98,-2.45 2.98,2.45, height 1.55
DW0028A_N [mm] "SOIC, 28-Leads, Body 17.9x7.5mm, Pitch 1.27mm, IPC Medium Density"
  oval 1.9x0.6 smd: 1(-4.75,8.255) 2(-4.75,6.985) 3(-4.75,5.715) 4(-4.75,4.445) 5(-4.75,3.175) 6(-4.75,1.905) 7(-4.75,0.635) 8(-4.75,-0.635) 9(-4.75,-1.905) 10(-4.75,-3.175) 11(-4.75,-4.445) 12(-4.75,-5.715) 13(-4.75,-6.985) 14(-4.75,-8.255) 15(4.75,-8.255) 16(4.75,-6.985) 17(4.75,-5.715) 18(4.75,-4.445) 19(4.75,-3.175) 20(4.75,-1.905) 21(4.75,-0.635) 22(4.75,0.635) 23(4.75,1.905) 24(4.75,3.175) 25(4.75,4.445) 26(4.75,5.715) 27(4.75,6.985) 28(4.75,8.255)
  silkscreen extent -5.6,-9.05 2.9,9.05, body extent -5.16,-8.95 5.16,8.95, height 2.54
FCC_disclaimer [mil]
Fiducial6.4-20 [mil]
  round 25 smd mask+26.87: 1(0,0)
  Top Layer keep-out circle w46.37: c0,0 r19.68
IEC_HighVoltage_Small [mil]
  silkscreen extent -107,-88 107,97
Keystone5002 [mil] "For Keystone 500x miniature loop terminals"
  round 80 hole 40: 1(0,0)
  silkscreen extent -58,-58 58,58, body extent -49,-49 49,49, height 182
Pb-Free_Overlay_Small [mil]
  silkscreen extent -46,-46 46,46
PK0003A_N [mm] "SOT89, 3-Leads, Body 4.5x2.5mm, Pitch 1.5mm, IPC Medium Density"
  rrect14% 1.6x0.7 smd: 1(-1.9,1.5) 3(-1.9,-1.5)
  rrect14% 1.7x0.7 smd: 2(-1.85,0)
  Top Layer region: -1,0.35 -0.35,1 2.05,1 2.7,0.35 2.7,-0.35 2.05,-1 -0.35,-1 -1,-0.35 -1.2,-0.35 -1.2,0.35
  silkscreen extent -2.5,-2.3 1.6,2.3, body extent -2.13,-2.25 1.96,2.25, height 1.6
SOD-123 [mm] "On Semi recommended land pattern"
  rect 0.915x1.22 smd: 1(-1.637,0) 2(1.637,0)
  silkscreen extent -2.74,-1.17 2.03,1.17, body extent -1.93,-0.9 1.93,0.9, height 1.35
sod-323 [mm] "NXP recommended land pattern"
  rect 0.6x0.6 smd paste-0.05: 1(-1.1,0) 2(1.1,0)
  silkscreen extent -2.06,-0.86 1.53,0.86, body extent -1.3,-0.67 1.3,0.68, height 1.1
SOD-523 [mm] "NXP Semiconductor recommended land pattern, nominal STEP model"
  rect 0.8x0.6 smd paste-0.05: 1(-0.55,0) 2(0.55,0)
  silkscreen extent -1.6,-0.64 1.2,0.63, body extent -0.8,-0.4 0.8,0.4, height 0.72
SOT-26 [mm] "SOT23, 6-Leads, Body 3.1x3.0mm (max), Pitch 0.95mm, IPC Medium Density based on Diodes Inc ap02002.pdf rev 29"
  rect 1.05x0.6 smd: 1(-1.225,0.95) 2(-1.225,0) 3(-1.225,-0.95) 4(1.225,-0.95) 5(1.225,0) 6(1.225,0.95)
  silkscreen extent -0.3,-1.55 0.3,1.55, body extent -1.5,-1.5 1.5,1.5, height 1.3
SOT-323 [mm] "Zetex recommended land pattern.  March 2007"
  rect 0.8x0.6 smd: 1(-0.8,0.65) 2(-0.8,-0.65) 3(0.8,0)
  silkscreen extent -1.14,-1.22 0.77,1.22, body extent -1.13,-1.13 1.12,1.12, height 1.13
SW_TL1015AF160QG [mm] "E-Switch"
  rect 0.95x1.4 smd: 1(-2.1,0) 2(2.1,0)
  silkscreen extent -2,-1.5 2,1.5, body extent -2.3,-1.5 2.3,1.5, height 2
TI_Stacked_Overlay_Small [mil]
  silkscreen extent -418,-98 418,98
TP_SM_1MM [mm] "1mm Test Point, SMT"
  round 1 smd paste-0.5: 1(0,0)
TRANS_NexFET_Q5A [mm] "TI recommended land pattern (nominal) M0139-01"
  rect 0.75x0.675 smd paste-0.1 mask+0.051: 1(-2.776,1.917) 2(-2.776,0.639) 3(-2.776,-0.639) 4(-2.776,-1.917)
  rect 0.655x0.675 smd paste-0.1 mask+0.051: 5(2.776,-1.917) 6(2.776,-0.639) 7(2.776,0.639) 8(2.776,1.917)
  rect 4.295x4.51 smd paste-2.2 mask+0.051: 9(0.301,0)
  silkscreen extent -3.4,-2.8 3.4,2.8, body extent -3.05,-2.5 3.05,2.5, height 1.11
WCAP-ATUL_1000x2500 [mm] "TH, 2-Leads, Dia 10mm, Pin Spacing 5mm"
  rect 1.4x1.4 hole 0.9: 1(-2.5,0)
  round 1.4 hole 0.9: 2(2.5,0)
  silkscreen extent -5.25,-5.25 5.25,5.25, body extent -5.21,-5.24 5.24,5.24, height 26.51
WE-LQS_4012 [mm] "SMD, 2-Leads, Body 3.7x4mm"
  rect 1.5x3.6 smd: 1(-1.525,0) 2(1.525,0)
  silkscreen extent -1.95,-2.1 1.95,2.1, body extent -1.95,-2.1 1.95,2.1, height 1.2
WE-PMI_1008 [mm] "WURTH"
  rect 0.8x2.2 smd: 1(-1,0) 2(1,0)
  body extent -1.35,-1.1 1.35,1.1, height 1
WL-SMCW_GREEN [mm] "WURTH"
  rect 0.8x0.8 smd: 1(-0.8,0) 2(0.8,0)
  silkscreen extent -1.9,-0.8 1.2,0.8, body extent -0.85,-0.45 0.85,0.45, height 0.8
WL-SMCW_RED [mm] "WURTH"
  rect 0.8x0.8 smd: 1(-0.8,0) 2(0.8,0)
  silkscreen extent -1.9,-0.8 1.2,0.8, body extent -0.85,-0.45 0.85,0.45, height 0.8
Wurth_61030421121 [mm] "Header, 2.54mm, 2x2, Gold, TH"
  rect 3.1x1 smd: 1(-2.7,1.27) 2(2.7,1.27) 3(-2.7,-1.27) 4(2.7,-1.27)
  silkscreen extent -2.54,-2.54 2.54,2.92, body extent -3.75,-2.54 3.75,2.54, height 9.6
Wurth_61031221121 [mm] "Header, 2.54mm, 6x2, Gold, TH"
  rect 3.1x1 smd: 1(-2.7,6.35) 2(2.7,6.35) 3(-2.7,3.81) 4(2.7,3.81) 5(-2.7,1.27) 6(2.7,1.27) 7(-2.7,-1.27) 8(2.7,-1.27) 9(-2.7,-3.81) 10(2.7,-3.81) 11(-2.7,-6.35) 12(2.7,-6.35)
  silkscreen extent -2.54,-7.62 2.54,8, body extent -3.75,-7.62 3.75,7.62, height 9.6
Wurth_691311500002 [mm] "Header (Shrouded), 5.08mm, 2x1, TH"
  rect 2.1x2.1 hole 1.6: 1(-2.54,0)
  round 2.1 hole 1.6: 2(2.54,0)
  silkscreen extent -5.5,-4.7 5.08,3.8, body extent -5.06,-4.7 5.1,3.8, height 12
Wurth_691311500103 [mm] "Header (Shrouded), 5.08mm, 3x1, TH"
  rect 2.1x2.1 hole 1.6: 1(-5.08,0)
  round 2.1 hole 1.6: 2(0,0) 3(5.08,0)
  Top Layer lines w0.1: 0.25,0 -0.25,0 ; 0,0.25 0,-0.25
  silkscreen extent -9.1,-4.7 8.62,3.8, body extent -8.62,-4.7 8.62,3.8, height 12

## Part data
3.3V 12V: "LED, Green, SMD"
C1 C6 C40 C50 C57: "CAP, CERM, 0.1 µF, 25 V, +/- 20%, X7R, 0402"
C2 C9 C18 C24: "CAP, CERM, 0.01 µF, 16 V, +/- 10%, X7R, 0402"
C3: "CAP, CERM, 0.1 µF, 16 V, +/- 20%, X5R, 0402"
C4 C8: "CAP, CERM, 1 µF, 16 V, +/- 20%, X5R, 0603"
C5 C17: "CAP, AL, 100 µF, 100 V, +/- 20%, 0.2 ohm, TH"
C7: "CAP, CERM, 4700 pF, 100 V, +/- 10%, X7R, 0402"
C10 C13 C22 C23 C25 C33 C66 C67 C68 C69 C70 C71 C72 C73: "CAP, CERM, 100 pF, 50 V, +/- 10%, X7R, 0402"
C11 C14: "CAP, CERM, 1 µF, 100 V, +/- 10%, X7S, 0805"
C12 C21: "CAP, CERM, 0.01 µF, 100 V, +/- 10%, X7R, 0603"
C15 C16 C26 C32: "CAP, CERM, 3.3 µF, 100 V, +/- 20%, X7S, 1206_190"
C19 C20: "CAP, CERM, 0.1 µF, 100 V, +/- 10%, X7R, 0805"
C27 C29 C51 C52: "CAP, CERM, 2200 pF, 100 V, +/- 5%, X7R, 0603"
C28 C64: "CAP, CERM, 4.7 µF, 25 V, +/- 10%, X5R, 0603"
C34 C39 C62: "CAP, CERM, 1 µF, 16 V, +/- 10%, X5R, 0603"
C36: "CAP, CERM, 3300 pF, 100 V, +/- 10%, X7R, 0603"
C37: "CAP, CERM, 0.1 µF, 100 V, +/- 10%, X7R, 0603"
C41: "CAP, CERM, 1000 pF, 25 V, +/- 10%, X7R, 0402"
CLR_FLT: "Switch, Tactile, SPST-NO, 0.05A, 12V, SMT"
D1: "Diode, Switching, 75 V, 0.15 A, SOT-323"
D3 D4 D5 D8 D13: "Diode, Ultrafast, 100 V, 0.25 A, SOD-323"
D6: "Diode, Zener, 3.9 V, 300 mW, SOD-523"
D9 D10: "Diode, Zener, 91 V, 500 mW, SOD-123"
"DANGER HIGH VOLTAGE" "DANGER HIGH VOLTAGE!": library part IEC_HighVoltage, "IEC 61010-1 High Voltage Warning"
FAULT PGOOD TRIP: "LED, Red, SMD"
FID1 FID2 FID3 FID4 FID5 FID6: "Fiducial mark.  There is nothing to buy or mount."
I_CS: library part TP_SM_1MM, "1mm Test Point, SMT"
J1: "Header (Shrouded), 5.08mm, 3x1, Tin, TH"
J2 J5: "Header, 2.54mm, 2x2, Gold, SMT"
J4: "Header (Shrouded), 5.08mm, 2x1, Tin, TH"
J7: "Header, 2.54mm, 6x2, Gold, SMT"
L2: "Inductor, Shielded Drum Core, Metal Composite, 10 µH, 0.35 A, 0.7 ohm, SMD"
L5: "Inductor, Wirewound, Ferrite, 100 µH, 0.35 A, 1.697 ohm, SMD"
Logo1: library part TI_Logo, "Texas Instrument Corporate Signature"
Logo2: library part Pb-Free
Logo3: library part FCC_disclaimer, "FCC_disclaimer"
Q1: library part "DMMT5551-7-F, Diodes Inc.", "Transistor, Dual NPN, 160 V, 0.2 A, SOT-26"
Q5 Q6 Q7 Q8: "MOSFET, N-CH, 100 V, 10 A, SON 5x6mm"
R1: "RES, 475, 1%, 0.063 W, 0402"
R2 R3 R4 R5 R15 R16 R27 R36: "RES, 22, 5%, 0.063 W, 0402"
R6: "RES, 806, 1%, 0.063 W, 0402"
R7: "RES, 487 k, 1%, 0.063 W, 0402"
R8: "RES, 100 k, 1%, 0.063 W, 0402"
R9: "RES, 0, 5%, 0.063 W, 0402"
R10 R50 R78: "RES, 10, 5%, 0.1 W, 0603"
R11: "RES, 24 k, 5%, 0.063 W, 0402"
R12: "RES, 33.2 k, 1%, 0.063 W, 0402"
R13 R14 R20: "RES, 1.2 k, 5%, 0.063 W, 0402"
R17: "RES, 100 k, 5%, 0.063 W, 0402"
R18 R19 R23 R24 R49 R76 R93 R126: "RES, 51 k, 5%, 0.063 W, 0402"
R21 R35 R40 R81 R83 R91: "RES, 49.9 k, 1%, 0.063 W, 0402"
R22: "RES, 1.00 k, 1%, 0.063 W, 0402"
R25: "RES, 820, 5%, 0.063 W, 0402"
R26: "RES, 6.8 k, 5%, 0.063 W, 0402"
R28 R29 R95 R96: "RES, 2.7, 5%, 0.125 W, 0805"
R51 R53: "RES, 1.50 k, 1%, 0.063 W, 0402"
R57: "RES, 100, 5%, 0.063 W, 0402"
R58 R67 R68 R74: "RES, 47, 5%, 0.1 W, 0603"
R61 R62: "RES, 3.0, 5%, 0.1 W, 0603"
R64: "RES, 0.01, 1%, 3 W, 2512"
R66: "RES, 1.8 k, 5%, 0.063 W, 0402"
R69: "RES, 23.2 k, 1%, 0.063 W, 0402"
R71 R97: "RES, 180 k, 5%, 0.063 W, 0402"
R72: "RES, 16.5 k, 1%, 0.063 W, 0402"
R73 R98: "RES, 10 k, 5%, 0.063 W, 0402"
R77: "RES, 9.1 k, 5%, 0.063 W, 0402"
R79 R80: "RES, 200 k, 5%, 0.063 W, 0402"
R82: "RES, 7.5 k, 5%, 0.063 W, 0402"
R85: "RES, 3.24 k, 1%, 0.063 W, 0402"
R92: "RES, 2.26 k, 1%, 0.063 W, 0402"
R101: "RES, 3.0, 5%, 0.063 W, 0402"
R102 R103: "RES, 3.32 k, 1%, 0.063 W, 0402"
R113: "RES, 3.09 k, 1%, 0.063 W, 0402"
R118: "RES, 10.0 k, 1%, 0.063 W, 0402"
R125: "RES, 20.0 k, 1%, 0.063 W, 0402"
TP1: "Test Point, Miniature, White, TH"
U1: "2.4V, 10µA, SC70, DSBGA Temperature Sensor, DCK0005A"
U2: "Photovoltaic Full Bridge Driver, DW0028A"
U3: "2.5V Low Iq Adjustable Precision Shunt Regulator, DBZ0003A"
U5: "100V, 300mA Constant On-Time Synchronous Buck Regulator, DDA0008B"
U6: "Quad Comparator, D0014A"
U7: "3-Terminal Adjustable Regulator, PK0003A"
U9: "SINGLE D-TYPE FLIP-FLOP WITH ASYNCHRONOUS CLEAR, DCK0006A"
U10: "Adjustable Precision Shunt Regulator, 34 ppm / degC, 100 mA, -40 to 125 degC, 3-pin SOT-23 (DBZ), Green (RoHS & no Sb/Br)"

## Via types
v1: diameter 20, hole 10, Top Layer to Bottom Layer, 355 vias
v2: diameter 40, hole 20, Top Layer to Bottom Layer, 7 vias
v3: diameter 25.98, hole 12.99, Top Layer to Bottom Layer, tented top, 4 vias
v4: diameter 240, hole 140, Top Layer to Bottom Layer, 4 vias

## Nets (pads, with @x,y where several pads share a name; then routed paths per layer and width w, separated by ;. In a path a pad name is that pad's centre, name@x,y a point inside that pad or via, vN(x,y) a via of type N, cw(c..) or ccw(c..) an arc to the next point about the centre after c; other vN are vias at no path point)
+3V3: C1.1 C24.1 C39.1 D1.2 J2.4 Q1.5 R1.2 R10.2 R14.2 R20.2 R25.2 U1.4 U7.2 | length 4036.2
  Top Layer w20: Q1.5@2888.23,1540 v1(2930,1540) 2953.62,1540 C24.1@2960,1533.62 ; R10.2@3771.5,2430 3781.5,2420 3880,2420 ; v2(3880,2540) 3880,2420 ; R1.2@3980,2403.62 R14.2@3930,2403.62 R20.2@3880,2403.62 3880,2420
  Top Layer w30: v2(3880,2540) U7.2@4022.83,2540 4117.51,2540
  Mid Layer w20: v1(2930,1540) 3020,1450 3510,1450 3570,1510 3600,1510 3880,1790 v2(3880,2540) ; v2(4145.53,2527.27) 4550,2931.74 v2(4550,3400)
  Bottom Layer w20: C1.1@3813.62,2480 3816.7,2483.08 U1.4@3816.7,2535.66 3821.05,2540 v2(3880,2540) ; v2(4145.53,2527.27) 4208.6,2464.19 D1.2@4454.25,2464.19
+4V: C9.1 D6.1 R13.1 R49.2 U9.3 U9.5 | length 432.1
  Top Layer w16: R49.2@3570,1570 3573.62,1566.38 U9.5@3629.33,1566.38 3662.65,1566.38 3688.24,1591.97 U9.3@3717.91,1591.97 3729.21,1591.97 3747.24,1610 C9.1@3772.65,1610 D6.1@3834.62,1610
  Top Layer w20: D6.1@3832.65,1608.03 3834.62,1610 3880,1655.38 R13.1@3880,1736.38
+12V: C18.1 C50.1 C57.1 C62.1 C64.1 D3.2 J2.2 R11.2 R13.2 R17.2 R18.1 R19.1 R26.2 R50.2 R77.2 R78.2 U6.3 U7.3 | length 5339.6
  Top Layer w20: C18.1@2623.62,1510 v1(2650,1510) R11.2@2676.38,1510 ; v1(3600,1470) 3620,1470 R17.2@3626.38,1476.38 ; R13.2@3880,1783.62 R19.1@3980,1783.62 ; C50.1@3973.62,1840 v1(3973.62,1815) 3973.62,1790 R19.1@3980,1783.62 ; v1(4030,2000) R26.2@4056.38,2000 ; U6.3@4240,1847.28 4240,1804.45 4219.17,1783.62 R19.1@3980,1783.62
  Mid Layer w20: v1(3600,1470) 3628.62,1470 v1(3973.62,1815) 4000,1841.38 4000,1970 v1(4030,2000)
  Mid Layer w30: v2(4410,2560) 4650,2800 v2(4650,3400)
  Bottom Layer w20: v1(2650,1510) 2665.13,1494.87 3134.87,1494.87 3684.33,2044.33 3684.33,2220
  Bottom Layer w30: R50.2@3481.5,2300 3604.33,2300 3684.33,2220 4090,2220 ; v1(4030,2000) 4090,2060 4090,2220 ; v2(4410,2560) 4310,2660 v2(4150,2660) 4090,2600 4090,2220
/FAULT2: FAULT.1 U2.15 | length 136
  Top Layer w20: U2.15@3655,2307.01 3655,2325 3690,2360 FAULT.1@3758.5,2360
BIN_2: R98.2 U2.4 | length 84.4
  Top Layer w20: R98.2@3155,1848.62 U2.4@3155,1932.99
BOUT_2: R15.2 R85.1 U2.11 | length 786.9
  Top Layer w20: U2.11@3505,1932.99 3505,1975 3540,2010 3930,2010 4000,2080 R85.1@4156.38,2080 R15.2@4156.38,2130
DC_LINK: D1.3 R16.2 R22.2 R81.1 | length 189
  Top Layer w20: R16.2@4570,2413.62 4573.62,2417.24 v1(4573.62,2450) R22.2@4573.62,2480 R81.1@4573.62,2540
  Bottom Layer w20: D1.3@4517.24,2438.6 4528.64,2450 v1(4573.62,2450)
FB: C40.2 R92.2 R125.1 U5.5 | length 182.5
  Top Layer w20: R92.2@4069.8,2947.68 U5.5@4141.14,2947.68 ; C40.2@4089.8,2884.92 R125.1@4139.8,2884.92 4144.8,2889.92 U5.5@4144.8,2944.02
